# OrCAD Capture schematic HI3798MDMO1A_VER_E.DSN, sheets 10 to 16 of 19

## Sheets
10 SHEET08: size Custom
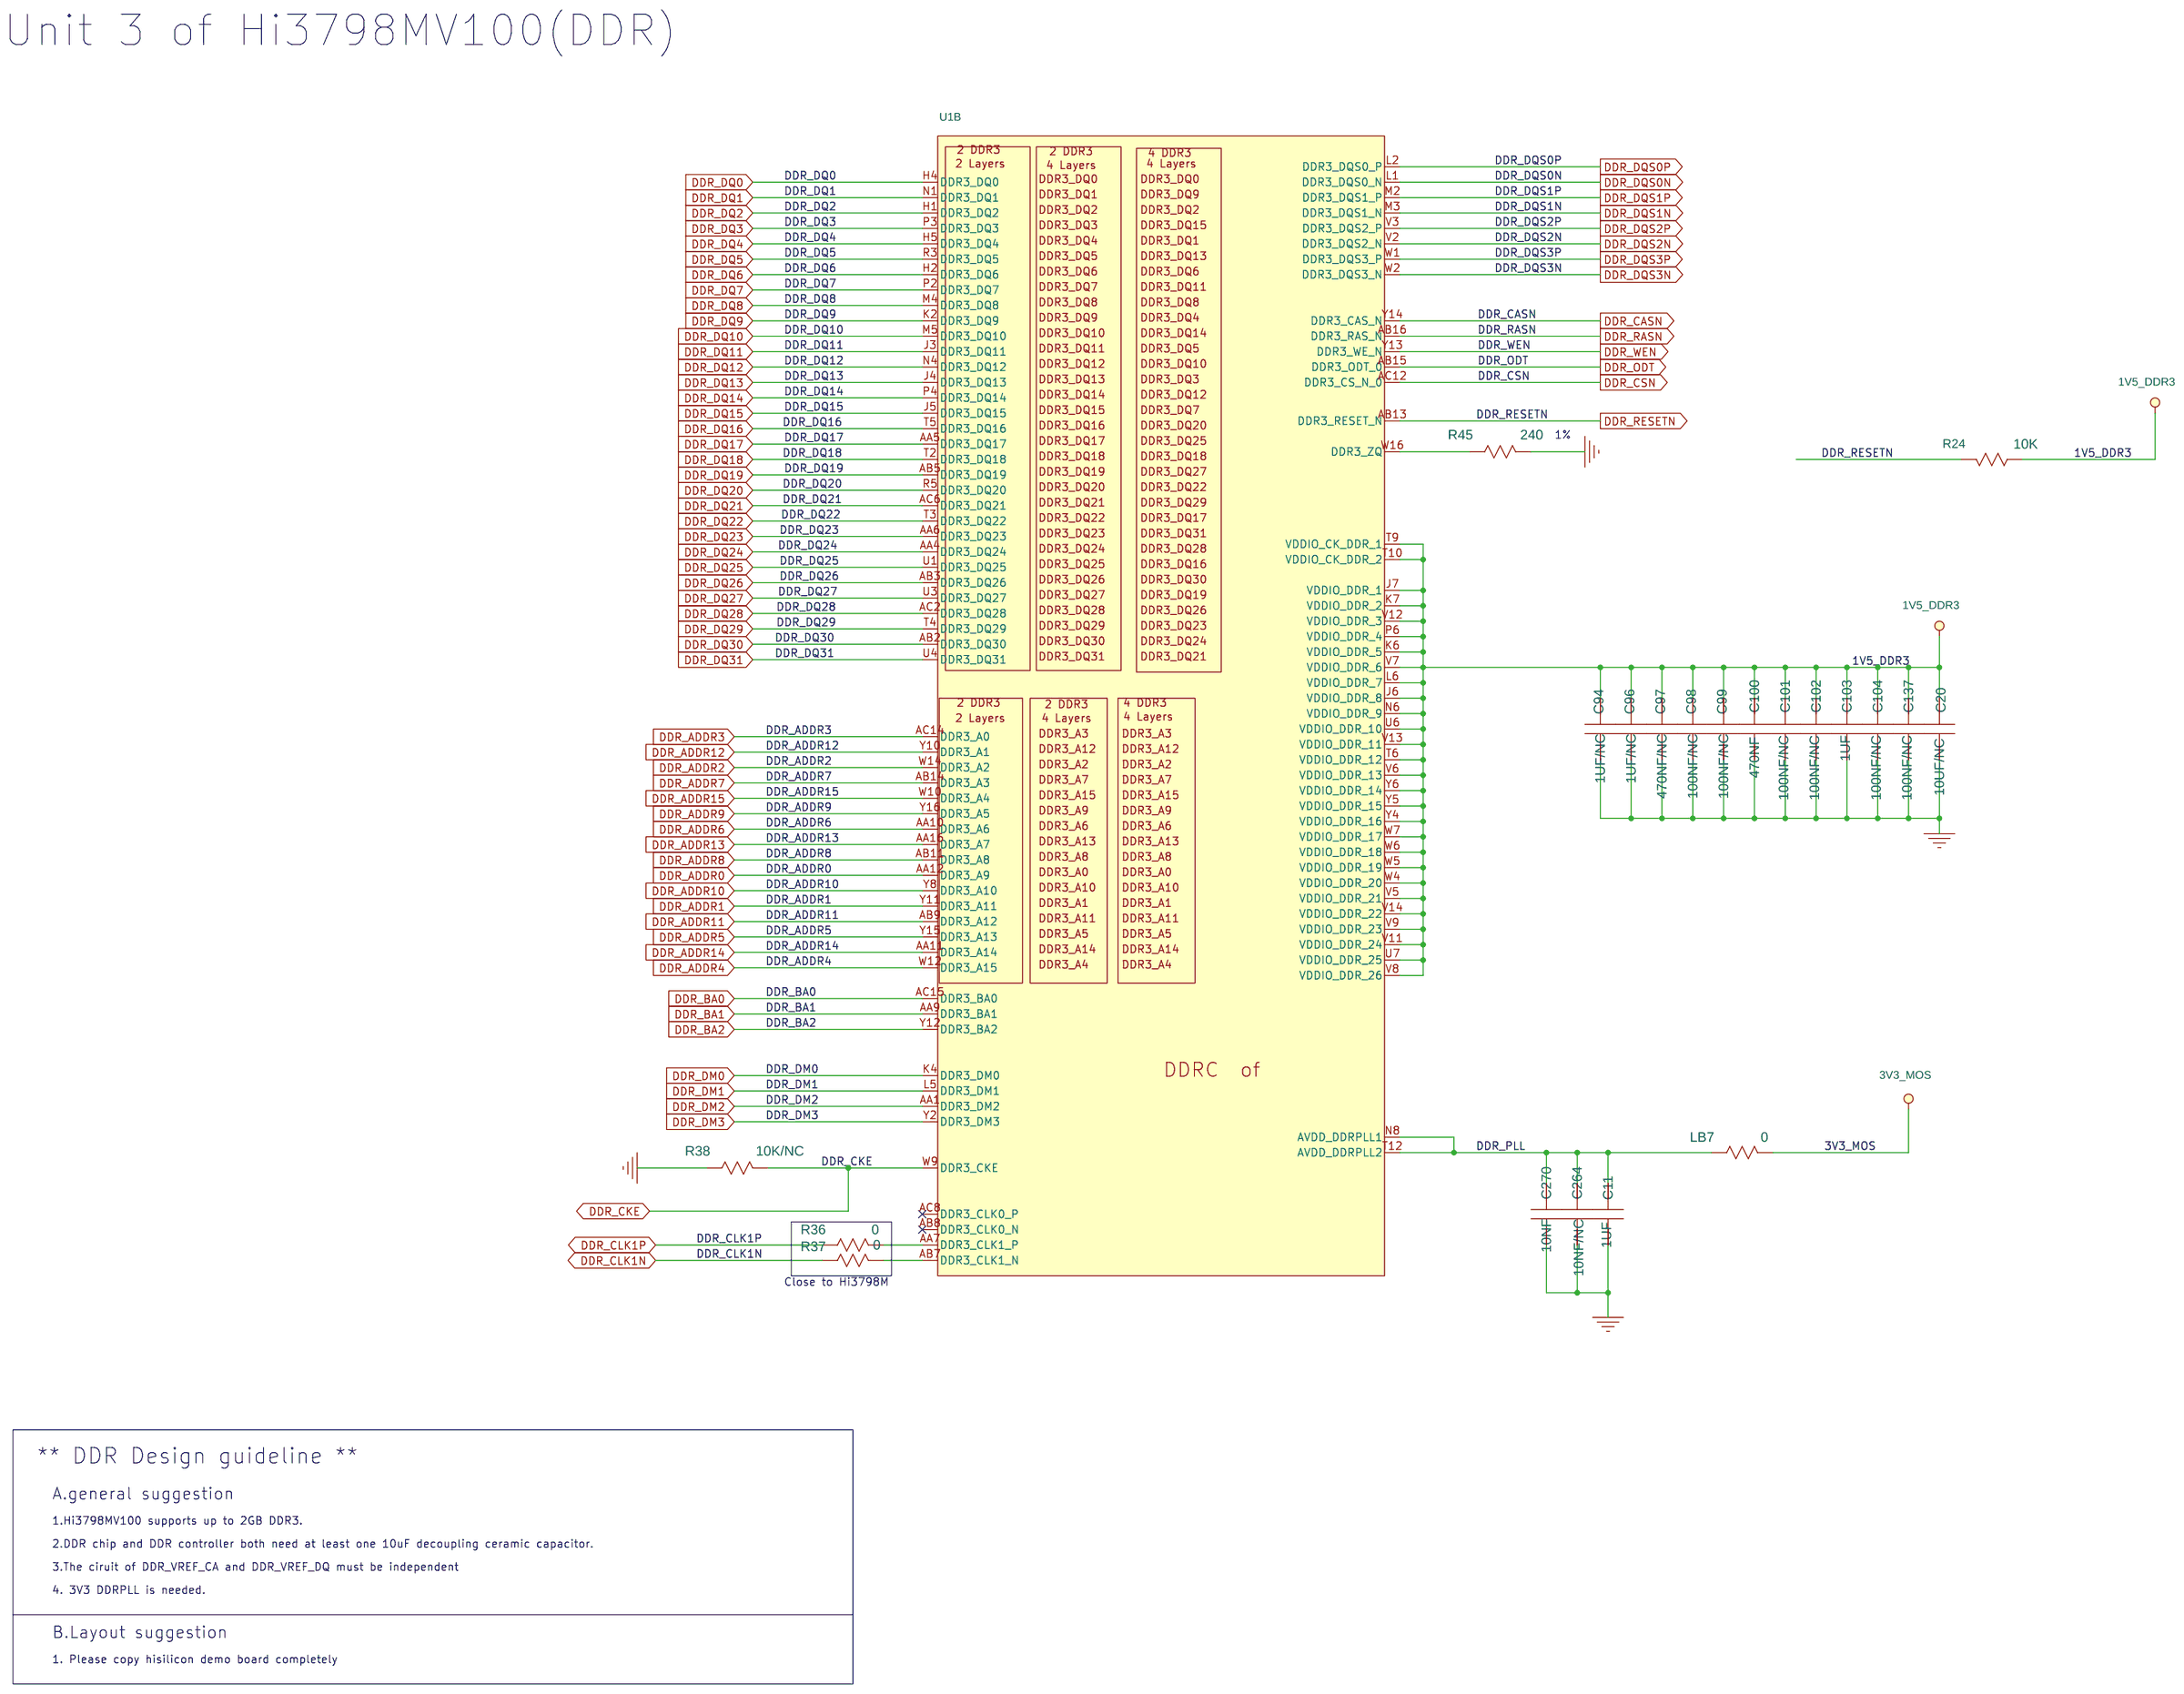
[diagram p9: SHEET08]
11 SHEET09: size Custom
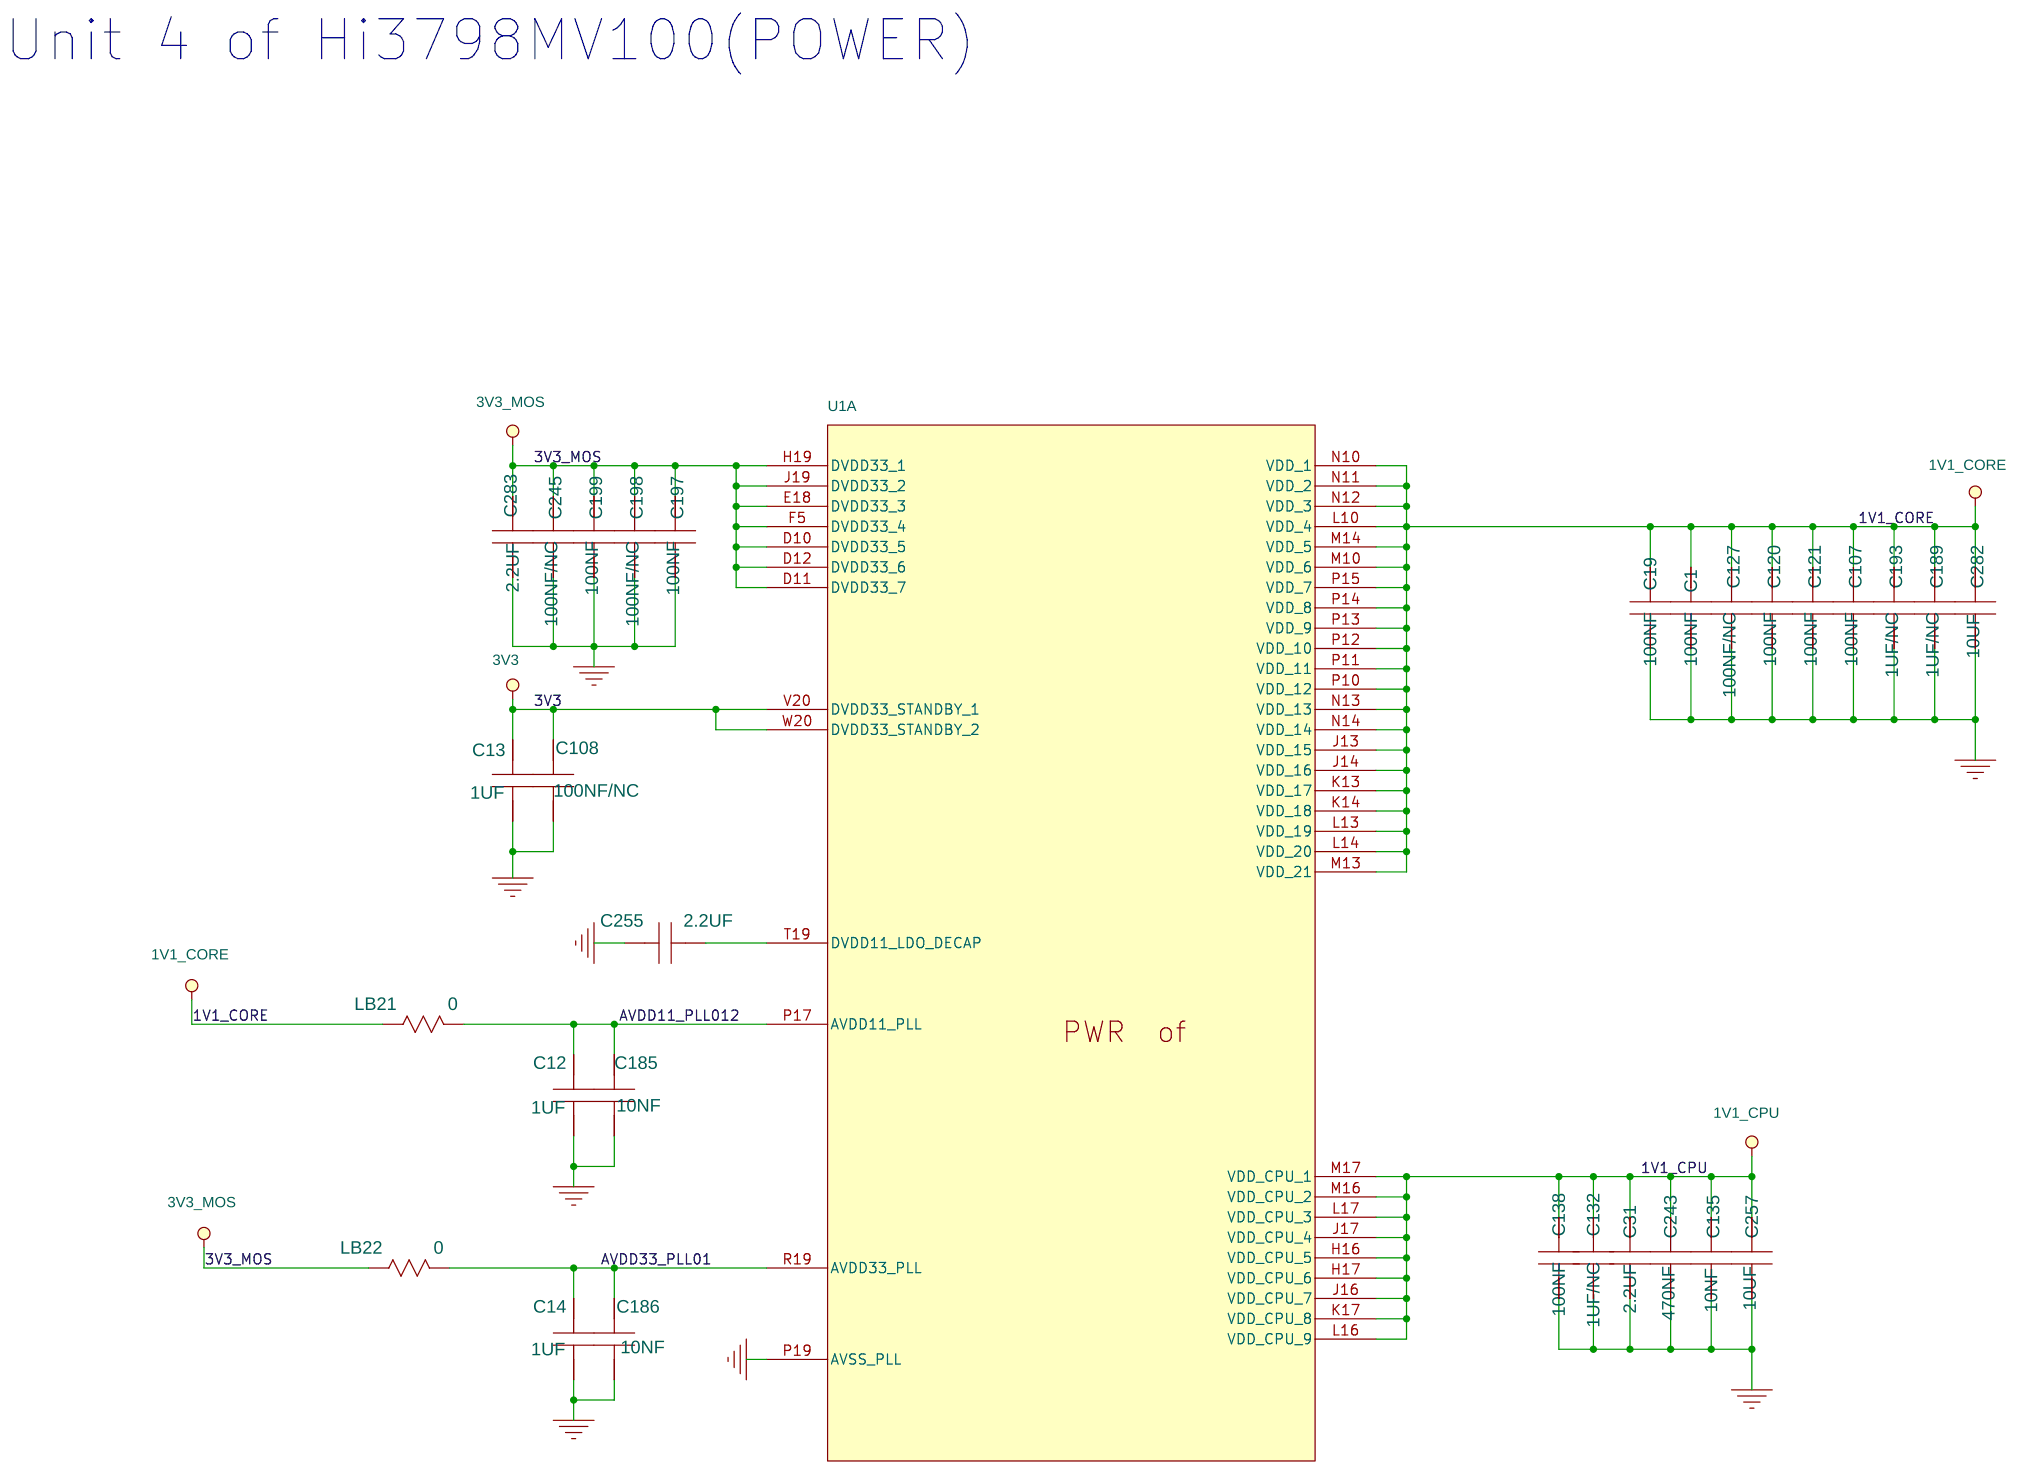
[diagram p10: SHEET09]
12 SHEET10: size Custom
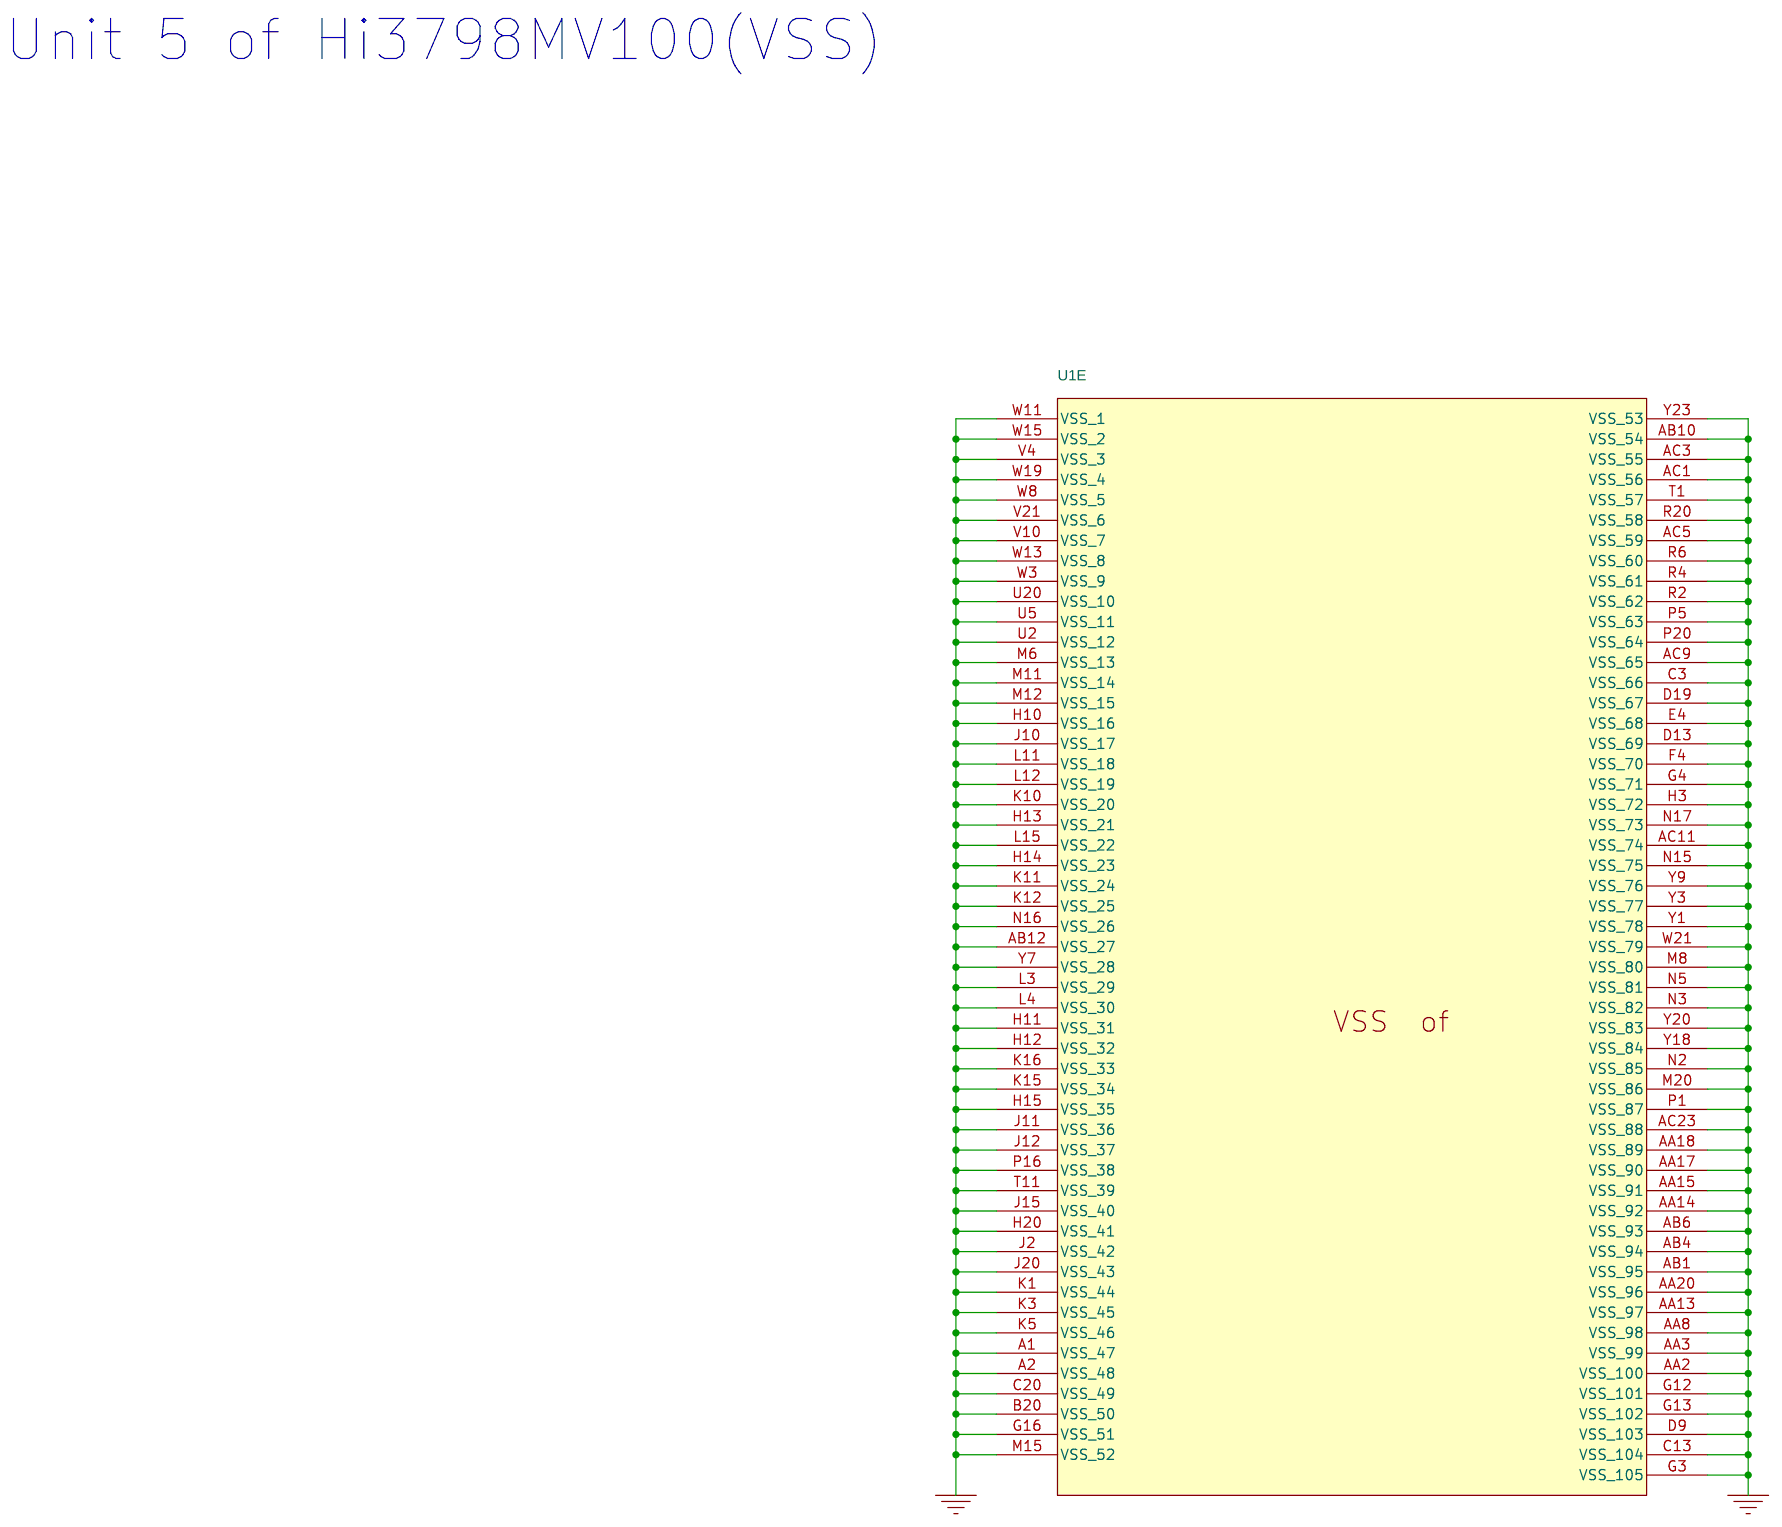
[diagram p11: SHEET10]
13 SHEET13: size Custom
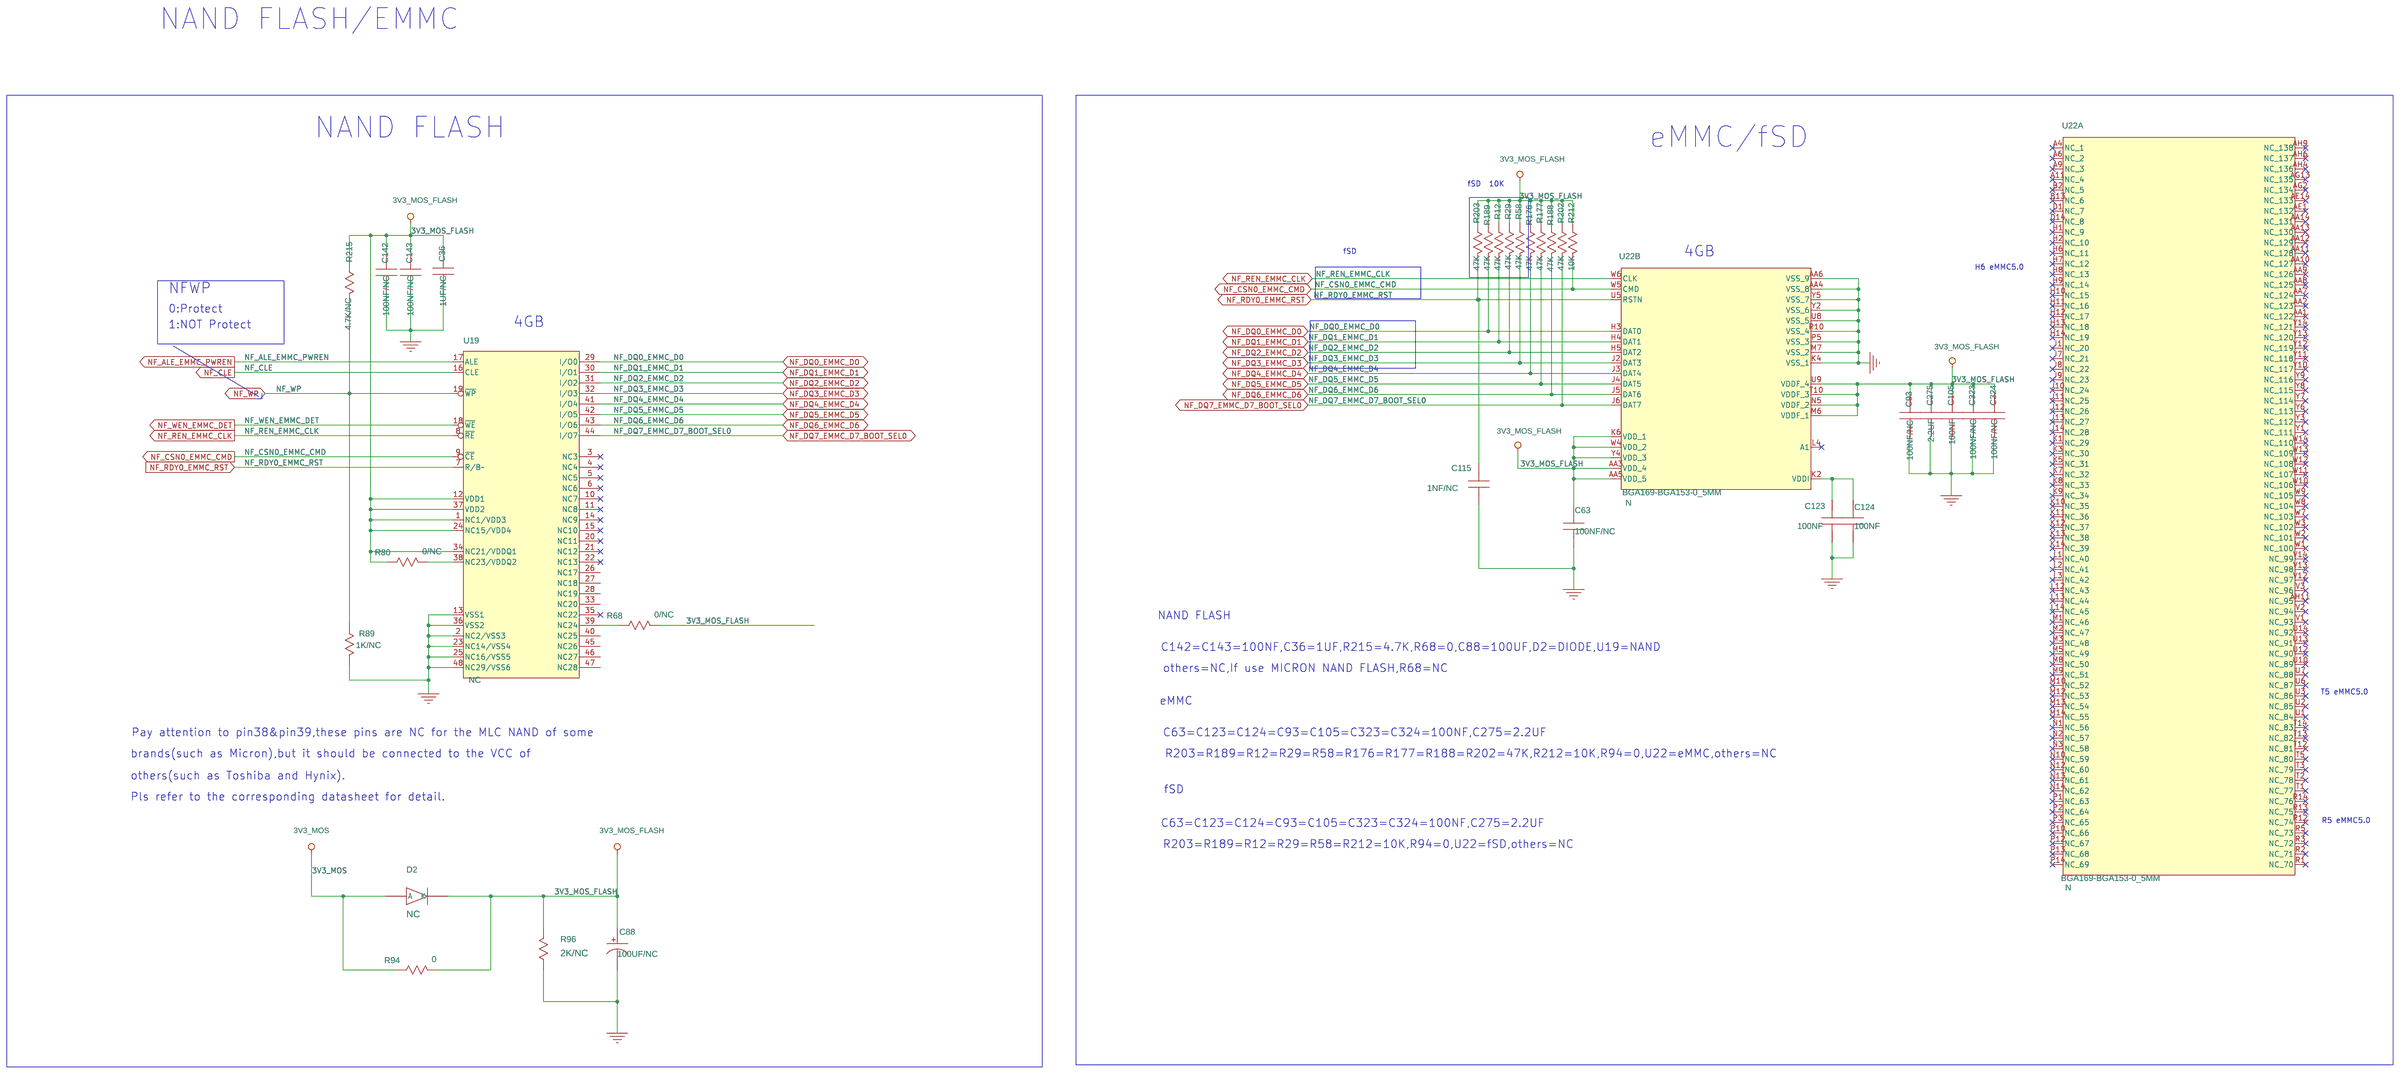
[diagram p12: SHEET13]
14 SHEET14: size Custom
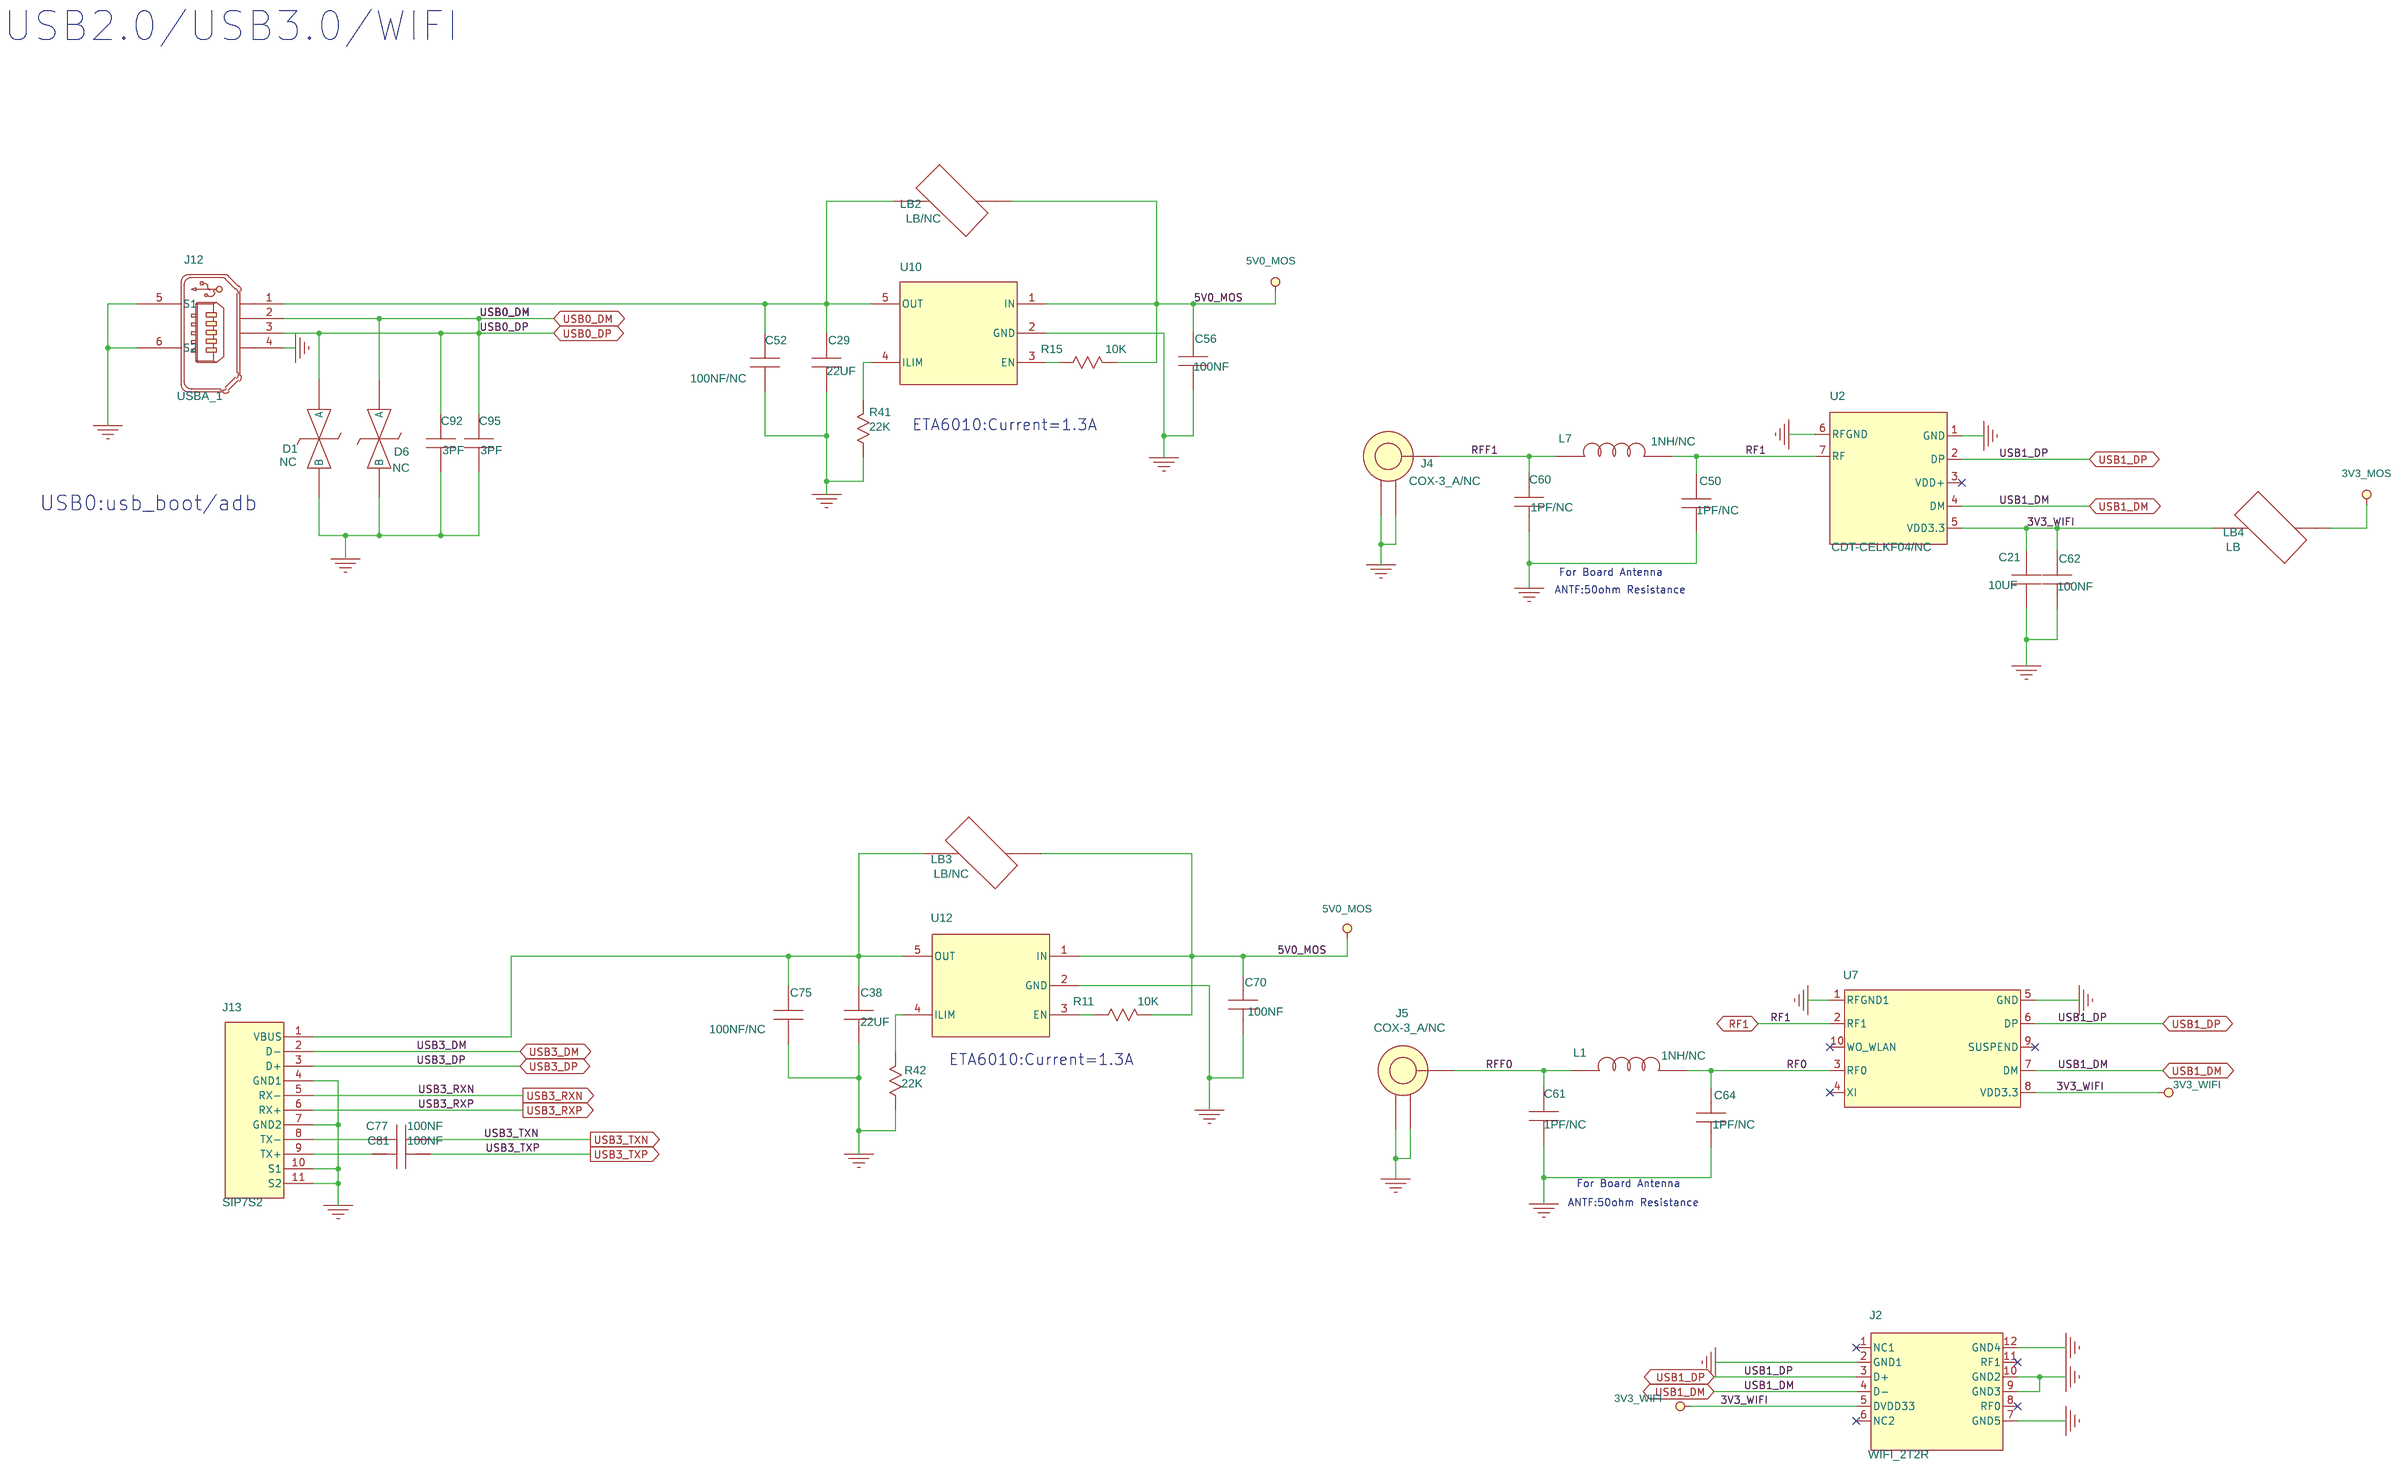
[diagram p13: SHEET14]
15 SHEET15: size Custom
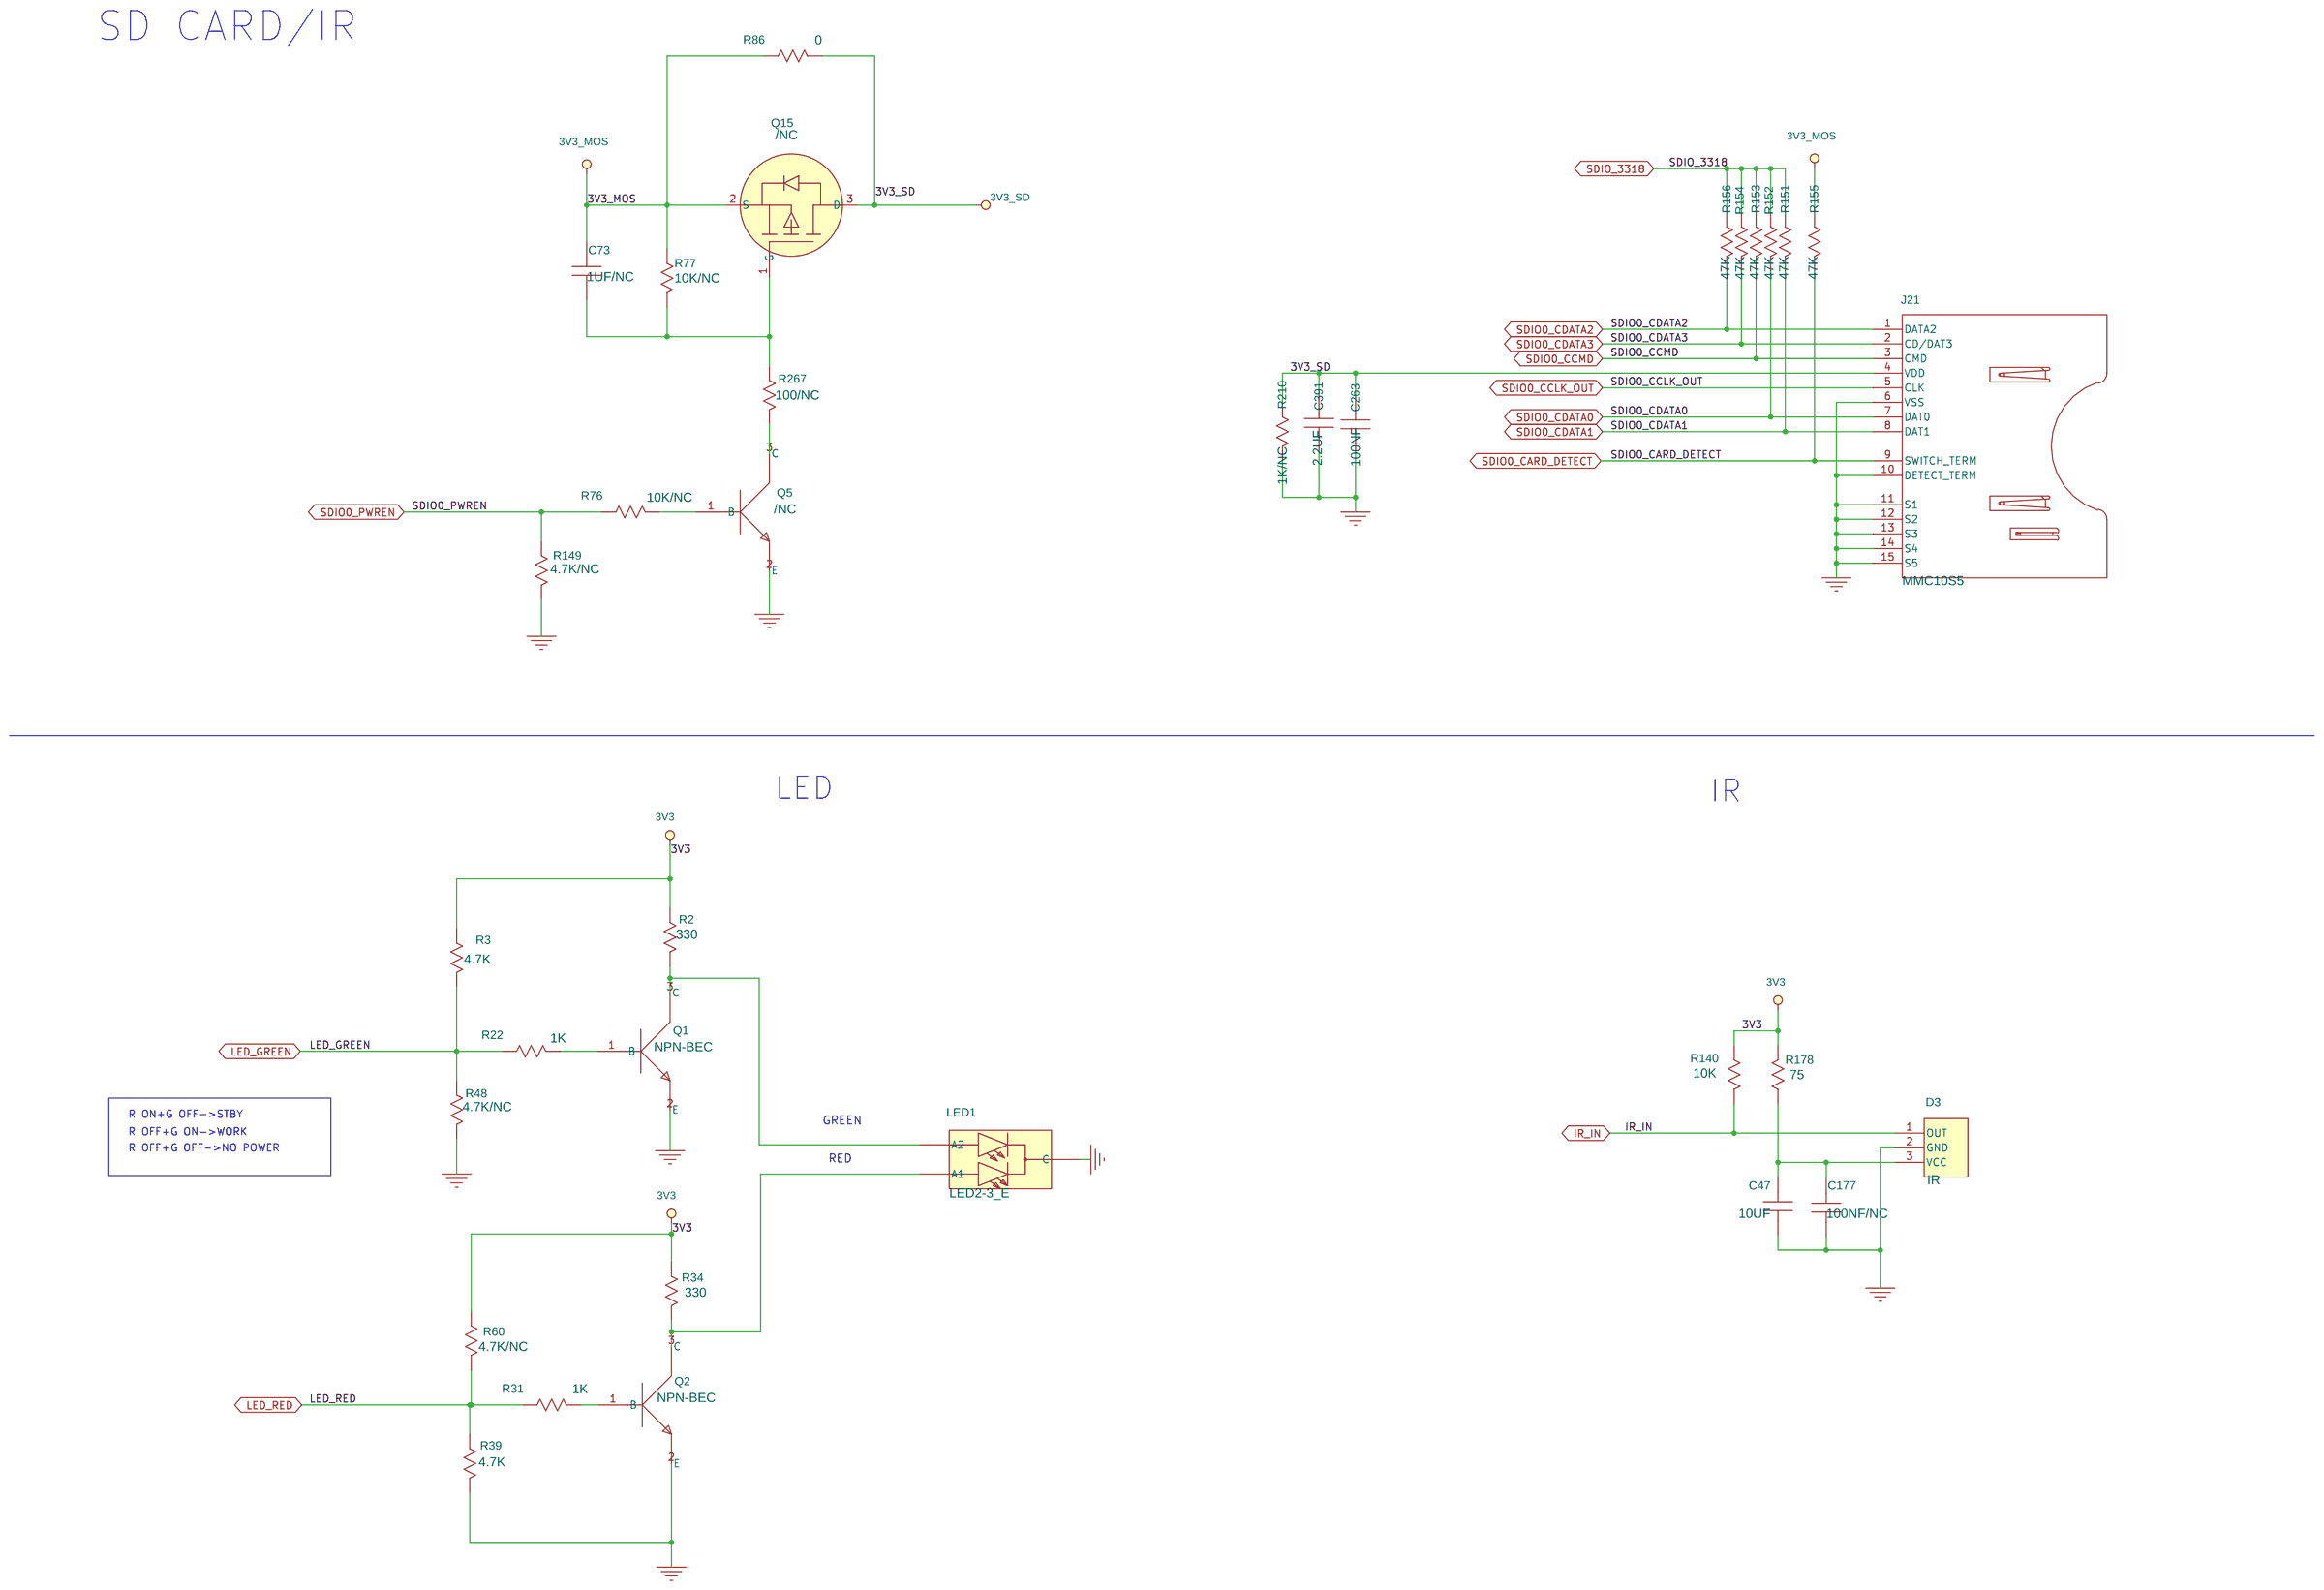
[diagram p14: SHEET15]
16 SHEET16: size Custom
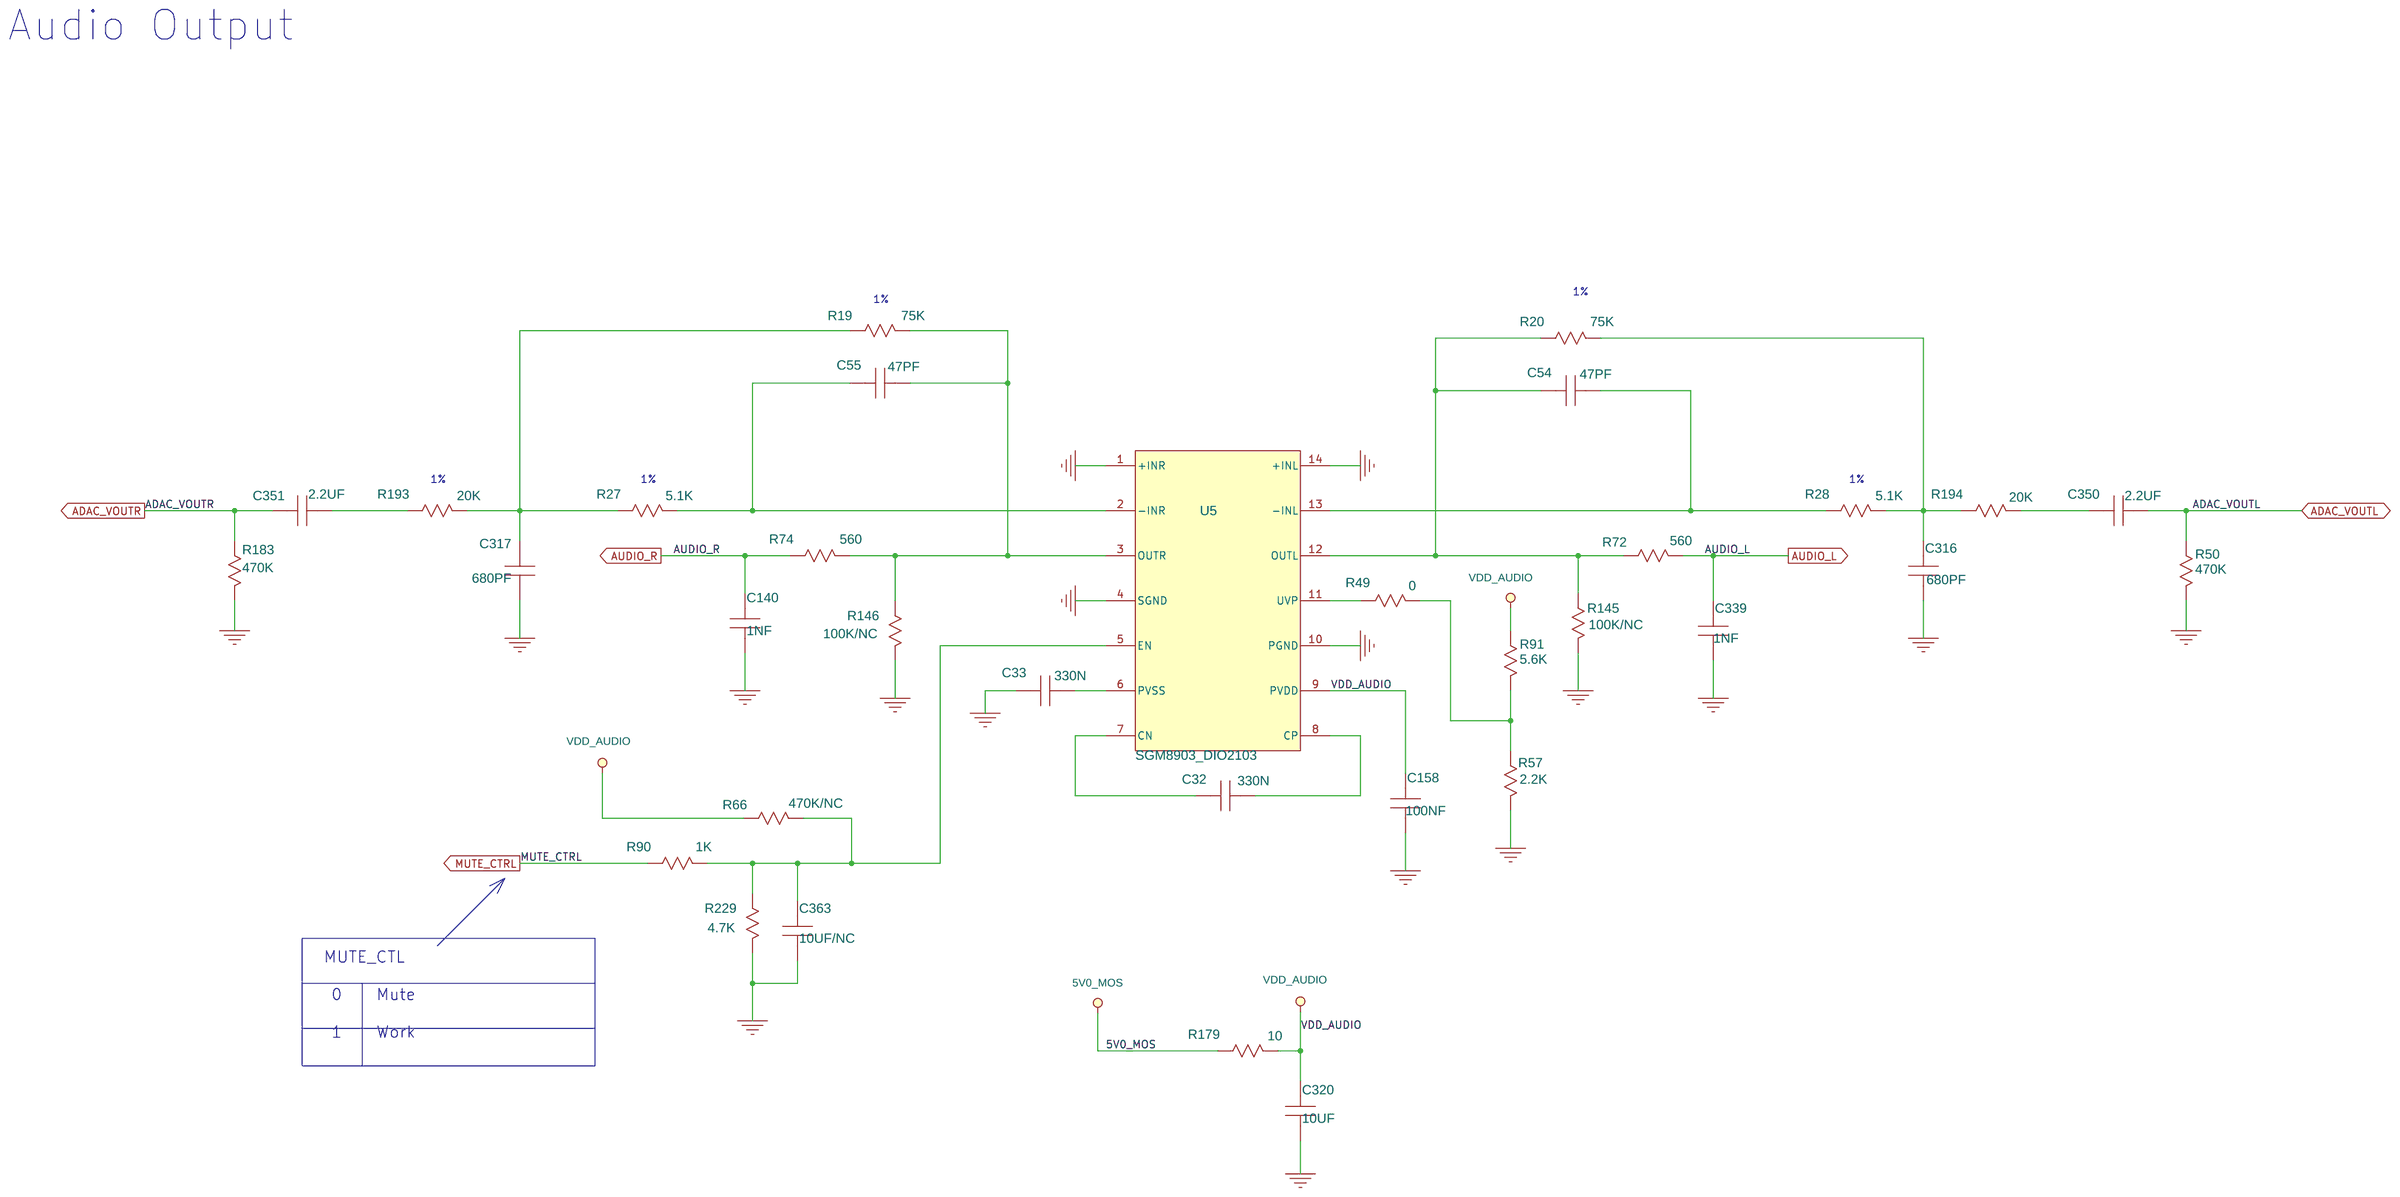
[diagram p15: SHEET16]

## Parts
sheet SHEET08
C11  1UF  [SC0603]
C20  10UF/NC  [SC0603]
C94  1UF/NC  [SC0402]
C96  1UF/NC  [SC0402]
C97  470NF/NC  [SC0402]
C98  100NF/NC  [SC0402]
C99  100NF/NC  [SC0402]
C100  470NF  [SC0402]
C101  100NF/NC  [SC0402]
C102  100NF/NC  [SC0402]
C103  1UF  [SC0402]
C104  100NF/NC  [SC0402]
C137  100NF/NC  [SC0402]
C264  10NF/NC  [SC0402]
C270  10NF  [SC0402]
LB7  0  [SL0603]
R24  10K  [SR0402]
R36  0  [SR0402]
R37  0  [SR0402]
R38  10K/NC  [SR0402]
R45  240  [SR0402]
sheet SHEET09
C1  100NF  [SC0402]
C12  1UF  [SC0402]
C13  1UF  [SC0603]
C14  1UF  [SC0402]
C19  100NF  [SC0402]
C31  2.2UF  [HSC0402]
C107  100NF  [SC0402]
C108  100NF/NC  [SC0402]
C120  100NF  [SC0402]
C121  100NF  [SC0402]
C127  100NF/NC  [SC0402]
C132  1UF/NC  [SC0402]
C135  10NF  [HSC0402]
C138  100NF  [SC0402]
C185  10NF  [SC0402]
C186  10NF  [SC0402]
C189  1UF/NC  [SC0402]
C193  1UF/NC  [SC0402]
C197  100NF  [SC0402]
C198  100NF/NC  [SC0402]
C199  100NF  [SC0402]
C243  470NF  [SC0402]
C245  100NF/NC  [SC0402]
C255  2.2UF  [HSC0402]
C257  10UF  [SC0603]
C282  10UF  [SC0603]
C283  2.2UF  [SC0603]
LB21  0  [SL0603]
LB22  0  [SL0603]
U1  S40V300_19X19  [TFBGA395-32-2323]  (sections A,B,C,D,E)
sheet SHEET13
C36  1UF/NC  [SC0603]
C63  100NF/NC  [SC0402]
C88  100UF/NC  [SAC6666]
C93  100NF/NC  [SC0402]
C105  100NF  [SC0402]
C115  1NF/NC  [SC0402]
C123  100NF  [SC0402]
C124  100NF  [SC0402]
C142  100NF/NC  [SC0402]
C143  100NF/NC  [SC0402]
C275  2.2UF  [SC0603]
C323  100NF/NC  [SC0402]
C324  100NF/NC  [SC0402]
D2  NC  [HSOD323A]
R12  47K  [SR0402]
R29  47K  [SR0402]
R58  47K  [SR0402]
R68  0/NC  [SR0402]
R80  0/NC  [SR0402]
R89  1K/NC  [SR0402]
R94  0  [SR1206]
R96  2K/NC  [SR0402]
R176  47K  [SR0402]
R177  47K  [SR0402]
R188  47K  [SR0402]
R189  47K  [SR0402]
R202  47K  [SR0402]
R203  47K  [SR0402]
R212  10K  [SR0402]
R215  4.7K/NC  [SR0402]
U19  NC  [SOP48-20-720B]
U22  N  [BGA169-BGA153-0_5MM]  (sections A,B)
sheet SHEET14
C21  10UF  [SC0603]
C29  22UF  [SC0805]
C38  22UF  [SC0805]
C50  1PF/NC  [SC0402]
C52  100NF/NC  [SC0603]
C56  100NF  [SC0603]
C60  1PF/NC  [SC0402]
C61  1PF/NC  [SC0402]
C62  100NF  [SC0603]
C64  1PF/NC  [SC0402]
C70  100NF  [SC0603]
C75  100NF/NC  [SC0603]
C77  100NF  [SC0402]
C81  100NF  [SC0402]
C92  3PF  [SC0402]
C95  3PF  [SC0402]
D1  NC  [SC0402]
D6  NC  [SC0402]
J2  WIFI_2T2R  [SIP12-2_0MM-1827]
J4  COX-3_A/NC  [HSCOX-AMC-TM-A]
J5  COX-3_A/NC  [HSCOX-AMC-TM-A]
J12  USBA_1  [USB4-1415]
J13  SIP7S2  [USB3_0_9P_DIP_MAINSUPER]
L1  1NH/NC  [SL0402]
L7  1NH/NC  [SL0402]
LB2  LB/NC  [SL0603]
LB3  LB/NC  [SL0603]
LB4  LB  [SL0805]
R11  10K  [SR0402]
R15  10K  [SR0402]
R41  22K  [SR0402]
R42  22K  [SR0402]
U2  CDT-CELKF04/NC  [CDTWIFI]
U7  NC  [CDTWIFI10]
U10  NC  [SOT23-5]
U12  NC  [SOT23-5]
sheet SHEET15
C47  10UF  [SC0603]
C73  1UF/NC  [SC0402]
C177  100NF/NC  [SC0402]
C263  100NF  [SC0603]
C391  2.2UF  [SC0603]
D3  IR  [SEN3-100C]
J21  MMC10S5  [MICRO_SD8-PUSH]
LED1  LED2-3_E  [LED3C-100C]
Q1  NPN-BEC  [SOT23]
Q2  NPN-BEC  [SOT23]
Q5  /NC  [SOT23]
Q15  /NC  [SOT23]
R2  330  [SR0402]
R3  4.7K  [SR0402]
R22  1K  [SR0402]
R31  1K  [SR0402]
R34  330  [SR0402]
R39  4.7K  [SR0402]
R48  4.7K/NC  [SR0402]
R60  4.7K/NC  [SR0402]
R76  10K/NC  [SR0603]
R77  10K/NC  [SR0603]
R86  0  [SR0603]
R140  10K  [SR0402]
R149  4.7K/NC  [SR0603]
R151  47K  [SR0402]
R152  47K  [SR0402]
R153  47K  [SR0402]
R154  47K  [SR0402]
R155  47K  [SR0402]
R156  47K  [SR0402]
R178  75  [SR0402]
R210  1K/NC  [SR0603]
R267  100/NC  [SR0603]
sheet SHEET16
C32  330N  [HSC0402]
C33  330N  [HSC0402]
C54  47PF  [SC0402]
C55  47PF  [SC0402]
C140  1NF  [SC0402]
C158  100NF  [SC0402]
C316  680PF  [SC0402]
C317  680PF  [SC0402]
C320  10UF  [SC0603]
C339  1NF  [SC0402]
C350  2.2UF  [SC0603]
C351  2.2UF  [SC0603]
C363  10UF/NC  [SC0603]
R19  75K  [SR0603]
R20  75K  [SR0603]
R27  5.1K  [SR0603]
R28  5.1K  [SR0603]
R49  0  [SR0402]
R50  470K  [SR0402]
R57  2.2K  [SR0402]
R66  470K/NC  [SR0402]
R72  560  [HSR0402]
R74  560  [HSR0402]
R90  1K  [SR0402]
R91  5.6K  [SR0402]
R145  100K/NC  [SR0402]
R146  100K/NC  [SR0402]
R179  10  [SR0603]
R183  470K  [SR0402]
R193  20K  [SR0402]
R194  20K  [SR0402]
R229  4.7K  [SR0402]
U5  SGM8903_DIO2103  [SGM8903]

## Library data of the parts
C11 C13 C36 = C: %182%%238%%182%%168%%185%%164%%215%%247%%181%%231%%209%%185%(V): 25; %195%%232%%202%%246%: SMD陶瓷电容-25V-1000NF-+/-10%-X7R-0603; %208%%161%%192%%224%%195%%251%%179%%198%: SMD陶瓷电容; CODE: 8070962; COMPONENT_HIGH_MAX: 0.9MM; DEVICE: CETMK107B7105KA_T
C20 = C: %182%%238%%182%%168%%185%%164%%215%%247%%181%%231%%209%%185%(V): 6.3; %195%%232%%202%%246%: SMD陶瓷电容-6.3V-10000NF-+/-10%-X7R-0805; %208%%161%%192%%224%%195%%251%%179%%198%: SMD陶瓷电容; CODE: 08070649; COMPONENT_HIGH_MAX: 0.9MM; DEVICE: C1608X5R0J106MT0A0E
C12 C14 C73 C94 C96 C103 C132 C189 C193 = C: %182%%238%%182%%168%%185%%164%%215%%247%%181%%231%%209%%185%(V): 10; %195%%232%%202%%246%: SMD陶瓷电容-10V-1000NF-+/-10%-X5R-0402-BT,TS16949; %208%%161%%192%%224%%195%%251%%179%%198%: SMD陶瓷电容; CODE: 8070612; COMPONENT_HIGH_MAX: 0.55MM; DEVICE: CV05X5R105K10AH
C97 C100 C243 = C: %182%%238%%182%%168%%185%%164%%215%%247%%181%%231%%209%%185%(V): 6.3; %195%%232%%202%%246%: SMD陶瓷电容-6.3V-470NF-+/-10%-X5R-0402; %208%%161%%192%%224%%195%%251%%179%%198%: SMD陶瓷电容; CODE: 8070625; COMPONENT_HIGH_MAX: 0.55MM; DEVICE: GRM155R60J474KE19D
C1 C19 C77 C81 C93 C98 C99 C101 C102 C104 C105 C107 C108 C115 C120 C121 C123 C124 C127 C137 C138 C197-C199 C245 C323 C324 = C: %182%%238%%182%%168%%185%%164%%215%%247%%181%%231%%209%%185%(V): 10; %195%%232%%202%%246%: SMD陶瓷电容-10V-100NF-+/-10%-X5R-0402; %208%%161%%192%%224%%195%%251%%179%%198%: SMD陶瓷电容; CODE: 8070561; COMPONENT_HIGH_MAX: 0.55MM; DEVICE: C0402C104K8PAC_7867
C135 C185 C186 C264 C270 = C: %182%%238%%182%%168%%185%%164%%215%%247%%181%%231%%209%%185%(V): 16; %195%%232%%202%%246%: SMD陶瓷电容-16V-10NF-+/-10%-X7R-0402-BT,TS16949; %208%%161%%192%%224%%195%%251%%179%%198%: SMD陶瓷电容; CODE: 8070449; COMPONENT_HIGH_MAX: 0.55MM; DEVICE: GRM155R71C103KA01D
LB7 LB21 LB22 = R: %182%%238%%182%%168%%185%%166%%194%%202%(W): 0.06; %195%%232%%202%%246%: 片式厚膜电阻器-0.0625W-0OHM-< 56MOHM-0402-1A-BT; %208%%161%%192%%224%%195%%251%%179%%198%: 片式厚膜电阻器; %215%%232%%214%%181%%212%%202%%208%%237%%198%%171%%178%%238%: < 50MOHM; CODE: 7090800; COMPONENT_HIGH_MAX: 0.4MM; DEVICE: RC0402JR_070R
R11 R15 R24 R212 = R: %182%%238%%182%%168%%185%%166%%194%%202%(W): 0.06; %195%%232%%202%%246%: 片式厚膜电阻器-0.0625W-10000OHM-+/-5%-0402-BT; %208%%161%%192%%224%%195%%251%%179%%198%: 片式厚膜电阻器; %215%%232%%214%%181%%212%%202%%208%%237%%198%%171%%178%%238%: +/-5%; CODE: 7090815; DEVICE: RC_02W103JT
R36 R37 R68 R80 = R: %182%%238%%182%%168%%185%%166%%194%%202%(W): 0.06; %195%%232%%202%%246%: 片式厚膜电阻器-0.0625W-0OHM-< 50MOHM-0402-1A-BT; %208%%161%%192%%224%%195%%251%%179%%198%: 片式厚膜电阻器; %215%%232%%214%%181%%212%%202%%208%%237%%198%%171%%178%%238%: < 50MOHM; CODE: 7090800; COMPONENT_HIGH_MAX: 0.4MM; DEVICE: RC0402JR_070R
R38 R140 = R: %182%%238%%182%%168%%185%%166%%194%%202%(W): 0.06; %195%%232%%202%%246%: 片式厚膜电阻器-0.0625W-10000OHM-+/-5%-0402-BT; %208%%161%%192%%224%%195%%251%%179%%198%: 片式厚膜电阻器; %215%%232%%214%%181%%212%%202%%208%%237%%198%%171%%178%%238%: +/-5%; CODE: 7090815; COMPONENT_HIGH_MAX: 0.4MM; DEVICE: RC_02W103JT
R45 = R: %182%%238%%182%%168%%185%%166%%194%%202%(W): 0.06; %195%%232%%202%%246%: 片式厚膜电阻器-0.0625W-240OHM-+/- 1%-0402-BT; %208%%161%%192%%224%%195%%251%%179%%198%: 片式厚膜电阻器; %215%%232%%214%%181%%212%%202%%208%%237%%198%%171%%178%%238%: +/- 1%; CODE: 7091782; COMPONENT_HIGH_MAX: 0.4MM; DEVICE: RC0402FR_07240RL
C31 C255 = C: %182%%238%%182%%168%%185%%164%%215%%247%%181%%231%%209%%185%(V): 6.3; %195%%232%%202%%246%: SMD陶瓷电容-6.3V-2200NF-+/-20%-X5R-0402-TS16949; %208%%161%%192%%224%%195%%251%%179%%198%: SMD陶瓷电容; CODE: 8070667; COMPONENT_HIGH_MAX: 0.6MM; DEVICE: GRM155R60J225ME15D
C21 C47 C257 C282 C320 C363 = C: %182%%238%%182%%168%%185%%164%%215%%247%%181%%231%%209%%185%(V): 6.3; %195%%232%%202%%246%: SMD陶瓷电容-6.3V-10000NF-+/-20%-X5R-0603-BT,TS16949; %208%%161%%192%%224%%195%%251%%179%%198%: SMD陶瓷电容; CODE: 8070649; COMPONENT_HIGH_MAX: 0.9MM; DEVICE: C1608X5R0J106MT0A0E
C283 = C: %182%%238%%182%%168%%185%%164%%215%%247%%181%%231%%209%%185%(V): 6.3; %195%%232%%202%%246%: SMD陶瓷电容-6.3V-2200NF-+/-10%-X5R-0603-BT; %208%%161%%192%%224%%195%%251%%179%%198%: SMD陶瓷电容; CODE: 8070563; COMPONENT_HIGH_MAX: 0.95MM; DEVICE: CM105X5R225K06AT
U1 = Hi3798MV100: DEVICE: HI3798MV100_A
C63 = C: %182%%238%%182%%168%%185%%164%%215%%247%%181%%231%%209%%185%(V): 50; %195%%232%%202%%246%: SMD陶瓷电容-50V-1NF-+/-10%-X7R-0402-BT; %208%%161%%192%%224%%195%%251%%179%%198%: SMD陶瓷电容; CODE: 8070531; COMPONENT_HIGH_MAX: 0.56MM; DEVICE: 04025C102KAT2A
C88 = CP: %182%%238%%182%%168%%185%%164%%215%%247%%181%%231%%209%%185%(V): 16; %195%%232%%202%%246%: 非固体SMD铝电容-16V-100UF-+/-20%-6.3*5.4MM-极性-105DEGC-1000H-片式,温度敏感器件-工艺耐温250DEGC,5S; %208%%161%%192%%224%%195%%251%%179%%198%: 非固体SMD铝电容; CODE: 8010269; COMPONENT_HIGH_MAX: 5.7MM; DEVICE: UWT1C101MCL1GB
C142 C143 C158 = C: %182%%238%%182%%168%%185%%164%%215%%247%%181%%231%%209%%185%(V): 16; %195%%232%%202%%246%: SMD陶瓷电容-16V-100NF-±10%-X7R-0402; %208%%161%%192%%224%%195%%251%%179%%198%: SMD陶瓷电容; CODE: 8070614; COMPONENT_HIGH_MAX: 0.6MM; DEVICE: RMEMK105BJ104KV_FR
C275 = C: %182%%238%%182%%168%%185%%164%%215%%247%%181%%231%%209%%185%(V): 6.3; %195%%232%%202%%246%: SMD陶瓷电容-6.3V-2200NF-+/-10%-X5R-0603; %208%%161%%192%%224%%195%%251%%179%%198%: SMD陶瓷电容; CODE: 8070563; COMPONENT_HIGH_MAX: 0.95MM; DEVICE: CM105X5R225K06AT
D2 = D_A: %195%%232%%202%%246%: 肖特基二极管-10V-3A-0.24V-SOD323-BT; %208%%161%%192%%224%%195%%251%%179%%198%: 肖特基二极管; CODE: 15010252; COMPONENT_HIGH_MAX: 1.1MM; DEVICE: BAT60BE6327
R12 R29 R49 R58 R151-R156 R176 R177 R188 R189 R202 R203 = R: %182%%238%%182%%168%%185%%166%%194%%202%(W): 0.06; %195%%232%%202%%246%: 片式厚膜电阻器-0.0625W-47000OHM-+/-5%-0402-ELOM; %208%%161%%192%%224%%195%%251%%179%%198%: 片式厚膜电阻器; %215%%232%%214%%181%%212%%202%%208%%237%%198%%171%%178%%238%: +/-5%; CODE: 7090819; DEVICE: RC0402JR_0747K
R89 R90 = R: %182%%238%%182%%168%%185%%166%%194%%202%(W): 0.06; %195%%232%%202%%246%: 片式厚膜电阻器-0.0625W-1000OHM-±5%-0402; %208%%161%%192%%224%%195%%251%%179%%198%: 片式厚膜电阻器; %215%%232%%214%%181%%212%%202%%208%%237%%198%%171%%178%%238%: ±5%; CODE: 7090809; COMPONENT_HIGH_MAX: 0.4MM; DEVICE: RC0402JR_071KL
R94 = R: %182%%238%%182%%168%%185%%166%%194%%202%(W): 0.06; %195%%232%%202%%246%: 片式厚膜电阻器-0.0625W-0OHM-< 50MOHM-0402-1A-BT; %208%%161%%192%%224%%195%%251%%179%%198%: 片式厚膜电阻器; %215%%232%%214%%181%%212%%202%%208%%237%%198%%171%%178%%238%: < 50MOHM; CODE: 07090002; COMPONENT_HIGH_MAX: 0.4MM; DEVICE: RC1206JR_070RL
R96 = R: %182%%238%%182%%168%%185%%166%%194%%202%(W): 0.06; %195%%232%%202%%246%: 片式厚膜电阻器-0.0625W-2000OHM-+/-1%-0402-BT; %208%%161%%192%%224%%195%%251%%179%%198%: 片式厚膜电阻器; %215%%232%%214%%181%%212%%202%%208%%237%%198%%171%%178%%238%: +/-1%; CODE: 7091354; COMPONENT_HIGH_MAX: 0.4MM; DEVICE: RC_02W2001FT
R215 = R: %182%%238%%182%%168%%185%%166%%194%%202%(W): 0.06; %195%%232%%202%%246%: 片式厚膜电阻器-0.0625W-4700OHM-+/-5%-0402; %208%%161%%192%%224%%195%%251%%179%%198%: 片式厚膜电阻器; %215%%232%%214%%181%%212%%202%%208%%237%%198%%171%%178%%238%: +/-5%; CODE: 7090793; COMPONENT_HIGH_MAX: 0.4MM; DEVICE: RK73B1ELTP472J
U19 = MLC_NAND_0: CODE: *
U22 = N_0: CaptureCellPackProp: NA
C29 C38 = C: %182%%238%%182%%168%%185%%164%%215%%247%%181%%231%%209%%185%(V): 6.3; %195%%232%%202%%246%: SMD陶瓷电容-6.3V-22000NF-+/-20%-X5R-0805-08070784编码拆分供华为技术使用; %208%%161%%192%%224%%195%%251%%179%%198%: SMD陶瓷电容; CODE: 8071114; COMPONENT_HIGH_MAX: 1.35MM; DEVICE: C2012X5R0J226MT000N
C50 C60 C61 C64 = C: %182%%238%%182%%168%%185%%164%%215%%247%%181%%231%%209%%185%(V): 50; %195%%232%%202%%246%: SMD陶瓷电容-50V-0.001NF-+/-0.1PF-NPO-0402-BT; %208%%161%%192%%224%%195%%251%%179%%198%: SMD陶瓷电容; CODE: 8070578; COMPONENT_HIGH_MAX: 0.55MM; DEVICE: GRM1555C1H1R0B
C52 C56 C62 C70 C75 C92 C95 C263 = C: %182%%238%%182%%168%%185%%164%%215%%247%%181%%231%%209%%185%(V): 50; %195%%232%%202%%246%: SMD陶瓷电容-50V-100NF-±10%-X7R-0603; %208%%161%%192%%224%%195%%251%%179%%198%: SMD陶瓷电容; CODE: 8070627; COMPONENT_HIGH_MAX: 0.9MM; DEVICE: C1608X7R1H104KT000N
D1 D6 = ULCE0505A015FR
J2 = WIFI_0
J4 J5 = COX-3_A: %195%%232%%202%%246%: 射频连接器-同轴连接器-50OHM-直式-MALE-SMT-终端专用-终端专用; %208%%161%%192%%224%%195%%251%%179%%198%: 射频连接器; CODE: 14240060; COMPONENT_HIGH_MAX: 1.45MM; DEVICE: 51_3612_50_H
J12 = USBA_1: CODE: 14080105
J13 = SIP7S2_0
L1 L7 = L: %195%%232%%202%%246%: 贴片电感器-0.001UH-5％-0.045OHM-1.36A-15DEGC-0402; %208%%161%%192%%224%%195%%251%%179%%198%: 贴片电感器; CODE: 10031232; COMPONENT_HIGH_MAX: 0.66MM; DEVICE: 0402CS_1N0XJLW
LB2 LB3 = LB_v2: %195%%232%%202%%246%: EMI磁珠-30OHM-0.05OHM-0.4A-0603-; %208%%161%%192%%224%%195%%251%%179%%198%: EMI磁珠; CODE: 10070003; COMPONENT_HIGH_MAX: 0.95MM; DEVICE: MGLB1608_030T_LF
LB4 = LB_v2: %195%%232%%202%%246%: EMI磁珠-+/-25%-220OHM-0.05OHM-2A-0805; %208%%161%%192%%224%%195%%251%%179%%198%: EMI磁珠; CODE: 10070012; COMPONENT_HIGH_MAX: 1.05MM; DEVICE: MGLB2012_220T_LF
R41 R42 = R: %182%%238%%182%%168%%185%%166%%194%%202%(W): 0.06; %195%%232%%202%%246%: 片式厚膜电阻器-0.0625W-22000OHM-+/-1%-0402; %208%%161%%192%%224%%195%%251%%179%%198%: 片式厚膜电阻器; %215%%232%%214%%181%%212%%202%%208%%237%%198%%171%%178%%238%: +/-1%; CODE: 7090798; COMPONENT_HIGH_MAX: 0.4MM; DEVICE: RK73H1ELTP2202F
U2 = CDT-CELKF04_0
U7 = CDT-CELKF10_0
U10 U12 = ETA6010: DEVICE: ETA6010_SGM2551A
C177 = C: %182%%238%%182%%168%%185%%164%%215%%247%%181%%231%%209%%185%(V): 16; %195%%232%%202%%246%: SMD陶瓷电容-16V-100NF-+/-10%-X7R-0402-BT; %208%%161%%192%%224%%195%%251%%179%%198%: SMD陶瓷电容; CODE: 8070614; COMPONENT_HIGH_MAX: 0.6MM; DEVICE: RMEMK105BJ104KV_FR
C350 C351 C391 = C: %182%%238%%182%%168%%185%%164%%215%%247%%181%%231%%209%%185%(V): 10; %195%%232%%202%%246%: SMD陶瓷电容-10V-2200NF-+/-10%-X5R-0603; %208%%161%%192%%224%%195%%251%%179%%198%: SMD陶瓷电容; CODE: 8070573; COMPONENT_HIGH_MAX: 0.9MM; DEVICE: GRM188R61A225KE34D
D3 = IRM-3638A_0: %195%%232%%202%%246%: 红外遥控接收头-5V-0.001A-0.015KM-38KHZ-940NM-7*8*3.75; %208%%161%%192%%224%%195%%251%%179%%198%: 红外遥控接收头; COMPONENT_HIGH_MAX: 6.95MM; DEVICE: TSOP4838
J21 = MMC10S5: %195%%232%%202%%246%: 板卡座类连接器-MICRO-SD卡座-8PIN-PUSH-PUSH-1.1MM-无锁扣-无-1MM-厚度1.45MM-终端专用; CODE: 14240249; COMPONENT_HIGH_MAX: 1.55MM; DEVICE: 5031820832
LED1 = LED2-3_E: %195%%232%%202%%246%: 发光二极管-0.25CD-红绿625NM/570NM-25MA-插装-共阴-终端专用-00500098; CODE: 15020190; COMPONENT_HIGH_MAX: 7.2MM; DEVICE: 209_3SYGSURC_S530_A3HW
Q1 Q2 Q5 = NPN-BEC: %195%%232%%202%%246%: 三极管-NPN-45V-100MA-225MW-200MV@100MA-SOT-23-180@2MA; %208%%161%%192%%224%%195%%251%%179%%198%: 三极管; CODE: 15050206; COMPONENT_HIGH_MAX: 1.26MM; DEVICE: BC847AE6327
Q15 = FETP-GSD: %195%%232%%202%%246%: MOSFET-P沟道--8V--3A-50MOHM--8V-SOT23; %208%%161%%192%%224%%195%%251%%179%%198%: MOSFET; CODE: 15060134; COMPONENT_HIGH_MAX: 1.11MM; DEVICE: IRLML6401TR
R2 R22 R31 R34 = R: %182%%238%%182%%168%%185%%166%%194%%202%(W): 0.06; %195%%232%%202%%246%: 片式厚膜电阻器-0.0625W-1000OHM-+/-5%-0402-BT; %208%%161%%192%%224%%195%%251%%179%%198%: 片式厚膜电阻器; %215%%232%%214%%181%%212%%202%%208%%237%%198%%171%%178%%238%: +/-5%; CODE: 7090809; COMPONENT_HIGH_MAX: 0.4MM; DEVICE: RC0402JR_071KL
R3 R39 R48 R60 R229 = R: %182%%238%%182%%168%%185%%166%%194%%202%(W): 0.06; %195%%232%%202%%246%: 片式厚膜电阻器-0.0625W-4700OHM-+/-5%-0402-BT; %208%%161%%192%%224%%195%%251%%179%%198%: 片式厚膜电阻器; %215%%232%%214%%181%%212%%202%%208%%237%%198%%171%%178%%238%: +/-5%; CODE: 7090793; COMPONENT_HIGH_MAX: 0.4MM; DEVICE: RK73B1ELTP472J
R76 R77 = R: %182%%238%%182%%168%%185%%166%%194%%202%(W): 0.1; %195%%232%%202%%246%: 片式厚膜电阻器-0.1W-10000OHM-+/-1%-0603; %208%%161%%192%%224%%195%%251%%179%%198%: 片式厚膜电阻器; %215%%232%%214%%181%%212%%202%%208%%237%%198%%171%%178%%238%: +/-1%; CODE: 7090889; COMPONENT_HIGH_MAX: 0.55MM; DEVICE: RC_03K1002FT
R86 = R: %182%%238%%182%%168%%185%%166%%194%%202%(W): 0.1; %195%%232%%202%%246%: 片式厚膜电阻器-0.1W-0OHM-<50MOHM-0603-1A-BT,TS16949; %208%%161%%192%%224%%195%%251%%179%%198%: 片式厚膜电阻器; %215%%232%%214%%181%%212%%202%%208%%237%%198%%171%%178%%238%: <50MOHM; CODE: 7090522; COMPONENT_HIGH_MAX: 0.55MM; DEVICE: RC0603JR_070RL
R149 = R: %182%%238%%182%%168%%185%%166%%194%%202%(W): 0.1; %195%%232%%202%%246%: 片式厚膜电阻器-0.1W-4700OHM-+/-5%-0603-抗硫化; %208%%161%%192%%224%%195%%251%%179%%198%: 片式厚膜电阻器; %215%%232%%214%%181%%212%%202%%208%%237%%198%%171%%178%%238%: +/-5%; CODE: 7090246; DEVICE: RC0603JR_074K7
R178 = R: %182%%238%%182%%168%%185%%166%%194%%202%(W): 0.06; %195%%232%%202%%246%: 片式厚膜电阻器-0.0625W-75OHM-+/-1%-0402; %208%%161%%192%%224%%195%%251%%179%%198%: 片式厚膜电阻器; %215%%232%%214%%181%%212%%202%%208%%237%%198%%171%%178%%238%: +/-1%; CODE: 7091321; COMPONENT_HIGH_MAX: 0.4MM; DEVICE: RC_02W750FT
R210 = R: %182%%238%%182%%168%%185%%166%%194%%202%(W): 0.1; %195%%232%%202%%246%: 片式厚膜电阻器-0.1W-1000OHM-+/-5%-0603; %208%%161%%192%%224%%195%%251%%179%%198%: 片式厚膜电阻器; %215%%232%%214%%181%%212%%202%%208%%237%%198%%171%%178%%238%: +/-5%; CODE: 7090277; COMPONENT_HIGH_MAX: 0.55MM; DEVICE: RC0603JR_071K
R267 = R: %182%%238%%182%%168%%185%%166%%194%%202%(W): 0.06; %195%%232%%202%%246%: 片式厚膜电阻器-0.1W-100OHM-±5%-0603; %208%%161%%192%%224%%195%%251%%179%%198%: 片式厚膜电阻器; %215%%232%%214%%181%%212%%202%%208%%237%%198%%171%%178%%238%: ±5%; CODE: 7090269; COMPONENT_HIGH_MAX: 0.55MM; DEVICE: RC0603JR_07100RL
C32 C33 = C: %195%%232%%202%%246%: SMD陶瓷电容-6.3V-330NF-+/-10%-X5R-0402-终端专用; %208%%161%%192%%224%%195%%251%%179%%198%: SMD陶瓷电容; CODE: 8070953; COMPONENT_HIGH_MAX: 0.55MM; DEVICE: C1005X5R0J334K
C54 C55 = C: %182%%238%%182%%168%%185%%164%%215%%247%%181%%231%%209%%185%(V): 50; %195%%232%%202%%246%: SMD陶瓷电容-50V-0.047NF-+/-5%-NP0-0402; %208%%161%%192%%224%%195%%251%%179%%198%: SMD陶瓷电容; CODE: 8070549; COMPONENT_HIGH_MAX: 0.55MM; DEVICE: C0402C470J5GAC_7867
C140 C339 = C: %182%%238%%182%%168%%185%%164%%215%%247%%181%%231%%209%%185%(V): 50; %195%%232%%202%%246%: SMD陶瓷电容-50V-1NF-+/-10%-X7R-0402-BT; %208%%161%%192%%224%%195%%251%%179%%198%: SMD陶瓷电容; CODE: 8070531; COMPONENT_HIGH_MAX: 0.55MM; DEVICE: 04025C102KAT2A
C316 C317 = C: %182%%238%%182%%168%%185%%164%%215%%247%%181%%231%%209%%185%(V): 50; %195%%232%%202%%246%: SMD陶瓷电容-50V-0.68NF-+/-5%-NP0-0402-供电专用-供电专用; %208%%161%%192%%224%%195%%251%%179%%198%: SMD陶瓷电容; CODE: 8070853; COMPONENT_HIGH_MAX: 0.55MM; DEVICE: C0402C681J5GAC7867
R19 R20 = R: %182%%238%%182%%168%%185%%166%%194%%202%(W): 0.1; %195%%232%%202%%246%: 片式厚膜电阻器-0.1W-75000OHM-+/-1% -0603; %208%%161%%192%%224%%195%%251%%179%%198%: 片式厚膜电阻器; %215%%232%%214%%181%%212%%202%%208%%237%%198%%171%%178%%238%: +/-1%; CODE: 7091238; COMPONENT_HIGH_MAX: 0.55MM; DEVICE: RK73H1JTTD7502F
R27 R28 = R: %182%%238%%182%%168%%185%%166%%194%%202%(W): 0.1; %195%%232%%202%%246%: 片式厚膜电阻器-0.1W-5100OHM-+/-1%-0603; %208%%161%%192%%224%%195%%251%%179%%198%: 片式厚膜电阻器; %215%%232%%214%%181%%212%%202%%208%%237%%198%%171%%178%%238%: +/-1%; CODE: 7091295; COMPONENT_HIGH_MAX: 0.55MM; DEVICE: RC0603FR_075K1L
R50 R183 = R: %182%%238%%182%%168%%185%%166%%194%%202%(W): 0.06; %195%%232%%202%%246%: 片式厚膜电阻器-0.0625W-470000OHM-±1%-0402; %208%%161%%192%%224%%195%%251%%179%%198%: 片式厚膜电阻器; %215%%232%%214%%181%%212%%202%%208%%237%%198%%171%%178%%238%: ±1%; CODE: 7090855; COMPONENT_HIGH_MAX: 0.4MM; DEVICE: RK73H1ETTP4703F
R57 = R: %182%%238%%182%%168%%185%%166%%194%%202%(W): 0.06; %195%%232%%202%%246%: 片式厚膜电阻器-0.0625W-2200OHM-+/-1%-0402--供电专用-07090810-供电专用; %208%%161%%192%%224%%195%%251%%179%%198%: 片式厚膜电阻器; %215%%232%%214%%181%%212%%202%%208%%237%%198%%171%%178%%238%: +/-1%; CODE: 7091537; COMPONENT_HIGH_MAX: 0.4MM; DEVICE: RC0402FR_072K2L2
R66 = R: %182%%238%%182%%168%%185%%166%%194%%202%(W): 0.06; %195%%232%%202%%246%: 片式厚膜电阻器-0.0625W-470000OHM-+/-1%-0402; %208%%161%%192%%224%%195%%251%%179%%198%: 片式厚膜电阻器; %215%%232%%214%%181%%212%%202%%208%%237%%198%%171%%178%%238%: +/-1%; CODE: 7090855; COMPONENT_HIGH_MAX: 0.4MM; DEVICE: RK73H1ETTP4703F
R72 R74 = R: %195%%232%%202%%246%: 片式厚膜电阻器-0.0625W-560OHM-+/-5%-0402-终端专用-终端专用; %208%%161%%192%%224%%195%%251%%179%%198%: 片式厚膜电阻器; CODE: 7091285; COMPONENT_HIGH_MAX: 0.4MM; DEVICE: RC0402JR_07560RL
R91 = R: %182%%238%%182%%168%%185%%166%%194%%202%(W): 0.06; %195%%232%%202%%246%: 片式厚膜电阻器-0.0625W-5600OHM-+/-1%-0402-BT; %208%%161%%192%%224%%195%%251%%179%%198%: 片式厚膜电阻器; %215%%232%%214%%181%%212%%202%%208%%237%%198%%171%%178%%238%: +/-1%; CODE: 7091275; COMPONENT_HIGH_MAX: 0.4MM; DEVICE: RK73H1ETTP5601F
R145 R146 = R: %182%%238%%182%%168%%185%%166%%194%%202%(W): 0.06; %195%%232%%202%%246%: 片式厚膜电阻器-0.0625W-100000OHM-+/-5%-0402-BT; %208%%161%%192%%224%%195%%251%%179%%198%: 片式厚膜电阻器; %215%%232%%214%%181%%212%%202%%208%%237%%198%%171%%178%%238%: +/-5%; CODE: 7090831; COMPONENT_HIGH_MAX: 0.4MM; DEVICE: RK73B1ELTP104J
R179 = R: %182%%238%%182%%168%%185%%166%%194%%202%(W): 0.1; %195%%232%%202%%246%: 片式厚膜电阻器-0.1W-10OHM-+/-5%-0603-TS16949; %208%%161%%192%%224%%195%%251%%179%%198%: 片式厚膜电阻器; %215%%232%%214%%181%%212%%202%%208%%237%%198%%171%%178%%238%: +/-5%; CODE: 7090264; COMPONENT_HIGH_MAX: 0.55MM; DEVICE: RC0603JR_0710R
R193 R194 = R: %182%%238%%182%%168%%185%%166%%194%%202%(W): 0.06; %195%%232%%202%%246%: 片式厚膜电阻器-0.0625W-20000OHM-+/-1%-0402-TS16949; %208%%161%%192%%224%%195%%251%%179%%198%: 片式厚膜电阻器; %215%%232%%214%%181%%212%%202%%208%%237%%198%%171%%178%%238%: +/-1%; CODE: 7091374; COMPONENT_HIGH_MAX: 0.4MM; DEVICE: RC_02W2002FT
U5 = SGM8903

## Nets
1V1_CORE: C1.1(A) C19.1(A) C107.1(A) C120.1(A) C121.1(A) C127.1(A) C189.1(A) C193.1(A) C282.1(A) LB21.1(A) U1.J13(VDD_15) U1.J14(VDD_16) U1.K13(VDD_17) U1.K14(VDD_18) U1.L10(VDD_4) U1.L13(VDD_19) U1.L14(VDD_20) U1.M10(VDD_6) U1.M13(VDD_21) U1.M14(VDD_5) U1.N10(VDD_1) U1.N11(VDD_2) U1.N12(VDD_3) U1.N13(VDD_13) U1.N14(VDD_14) U1.P10(VDD_12) U1.P11(VDD_11) U1.P12(VDD_10) U1.P13(VDD_9) U1.P14(VDD_8) U1.P15(VDD_7) ; also on sheet 6 8 9
1V1_CPU: C31.1(A) C132.1(A) C135.1(A) C138.1(A) C243.1(A) C257.1(A) U1.H16(VDD_CPU_5) U1.H17(VDD_CPU_6) U1.J16(VDD_CPU_7) U1.J17(VDD_CPU_4) U1.K17(VDD_CPU_8) U1.L16(VDD_CPU_9) U1.L17(VDD_CPU_3) U1.M16(VDD_CPU_2) U1.M17(VDD_CPU_1) ; also on sheet 6
1V5_DDR3: C20.1(A) C94.1(A) C96.1(A) C97.1(A) C98.1(A) C99.1(A) C100.1(A) C101.1(A) C102.1(A) C103.1(A) C104.1(A) C137.1(A) R24.2(B) U1.J6(VDDIO_DDR_8) U1.J7(VDDIO_DDR_1) U1.K6(VDDIO_DDR_5) U1.K7(VDDIO_DDR_2) U1.L6(VDDIO_DDR_7) U1.N6(VDDIO_DDR_9) U1.P6(VDDIO_DDR_4) U1.T6(VDDIO_DDR_12) U1.T9(VDDIO_CK_DDR_1) U1.T10(VDDIO_CK_DDR_2) U1.U6(VDDIO_DDR_10) U1.U7(VDDIO_DDR_25) U1.V5(VDDIO_DDR_21) U1.V6(VDDIO_DDR_13) U1.V7(VDDIO_DDR_6) U1.V8(VDDIO_DDR_26) U1.V9(VDDIO_DDR_23) U1.V11(VDDIO_DDR_24) U1.V12(VDDIO_DDR_3) U1.V13(VDDIO_DDR_11) U1.V14(VDDIO_DDR_22) U1.W4(VDDIO_DDR_20) U1.W5(VDDIO_DDR_19) U1.W6(VDDIO_DDR_18) U1.W7(VDDIO_DDR_17) U1.Y4(VDDIO_DDR_16) U1.Y5(VDDIO_DDR_15) U1.Y6(VDDIO_DDR_14) ; also on sheet 1 2 6
3V3: C13.1(A) C108.1(A) R2.1(A) R3.1(A) R34.1(A) R60.1(A) R140.2(B) R178.2(B) U1.V20(DVDD33_STANDBY_1) U1.W20(DVDD33_STANDBY_2) ; also on sheet 6 7 8 17
3V3_MOS: C73.1(A) C197.1(A) C198.1(A) C199.1(A) C245.1(A) C283.1(A) D2.2(A) LB4.2 LB7.2(B) LB22.1(A) Q15.2(S) R77.1(A) R86.1(A) R94.1(A) R155.1(A) U1.D10(DVDD33_5) U1.D11(DVDD33_7) U1.D12(DVDD33_6) U1.E18(DVDD33_3) U1.F5(DVDD33_4) U1.H19(DVDD33_1) U1.J19(DVDD33_2) ; also on sheet 7 8 9 17 18 19
3V3_MOS_FLASH: C36.1(A) C63.1(A) C88.1 C93.1(A) C105.1(A) C142.1(A) C143.1(A) C275.1(A) C323.1(A) C324.1(A) D2.1(K) R12.1(A) R29.1(A) R58.1(A) R68.2(B) R80.1(A) R94.2(B) R96.2(B) R176.1(A) R177.1(A) R188.1(A) R189.1(A) R202.1(A) R203.1(A) R212.1(A) R215.1(A) U19.1(NC1/VDD3) U19.12(VDD1) U19.24(NC15/VDD4) U19.34(NC21/VDDQ1) U19.37(VDD2) U22.AA3(VDD_4) U22.AA5(VDD_5) U22.K6(VDD_1) U22.M6(VDDF_1) U22.N5(VDDF_2) U22.T10(VDDF_3) U22.U9(VDDF_4) U22.W4(VDD_2) U22.Y4(VDD_3)
3V3_SD: C263.1(A) C391.1(A) J21.4(VDD) Q15.3(D) R86.2(B) R210.1(A)
3V3_WIFI: C21.1(A) C62.1(A) J2.5(DVDD33) LB4.1 U2.5(VDD3.3) U7.8(VDD3.3)
5V0_MOS: C56.1(A) C70.1(A) LB2.2 LB3.2 R11.2(B) R15.2(B) R179.1(A) U10.1(IN) U12.1(IN) ; also on sheet 7 19
AVDD11_PLL012: C12.1(A) C185.1(A) LB21.2(B) U1.P17(AVDD11_PLL)
AVDD33_PLL01: C14.1(A) C186.1(A) LB22.2(B) U1.R19(AVDD33_PLL)
GND: C1.2(B) C11.2(B) C12.2(B) C13.2(B) C14.2(B) C19.2(B) C20.2(B) C21.2(B) C29.2(B) C31.2(B) C33.1(A) C36.2(B) C38.2(B) C47.2(B) C50.2(B) C52.2(B) C56.2(B) C60.2(B) C61.2(B) C62.2(B) C63.2(B) C64.2(B) C70.2(B) C75.2(B) C88.2 C92.2(B) C93.2(B) C94.2(B) C95.2(B) C96.2(B) C97.2(B) C98.2(B) C99.2(B) C100.2(B) C101.2(B) C102.2(B) C103.2(B) C104.2(B) C105.2(B) C107.2(B) C108.2(B) C115.2(B) C120.2(B) C121.2(B) C123.2(B) C124.2(B) C127.2(B) C132.2(B) C135.2(B) C137.2(B) C138.2(B) C140.2(B) C142.2(B) C143.2(B) C158.2(B) C177.2(B) C185.2(B) C186.2(B) C189.2(B) C193.2(B) C197.2(B) C198.2(B) C199.2(B) C243.2(B) C245.2(B) C255.1(A) C257.2(B) C263.2(B) C264.2(B) C270.2(B) C275.2(B) C282.2(B) C283.2(B) C316.2(B) C317.2(B) C320.2(B) C323.2(B) C324.2(B) C339.2(B) C363.2(B) C391.2(B) D1.2(B) D3.2(GND) D6.2(B) J2.2(GND1) J2.7(GND5) J2.9(GND3) J2.10(GND2) J2.12(GND4) J4.2 J4.3 J5.2 J5.3 J12.4 J12.5(S1) J12.6(S2) J13.4(GND1) J13.7(GND2) J13.10(S1) J13.11(S2) J21.6(VSS) J21.10(DETECT_TERM) J21.11(S1) J21.12(S2) J21.13(S3) J21.14(S4) J21.15(S5) LED1.2(C) Q1.2(E) Q2.2(E) Q5.2(E) R38.1(A) R39.2(B) R41.1(A) R42.1(A) R45.2(B) R48.2(B) R50.2(B) R57.2(B) R89.2(B) R96.1(A) R145.2(B) R146.2(B) R149.2(B) R183.2(B) R210.2(B) R229.2(B) U1.A1(VSS_47) U1.A2(VSS_48) U1.AA2(VSS_100) U1.AA3(VSS_99) U1.AA8(VSS_98) U1.AA13(VSS_97) U1.AA14(VSS_92) U1.AA15(VSS_91) U1.AA17(VSS_90) U1.AA18(VSS_89) U1.AA20(VSS_96) U1.AB1(VSS_95) U1.AB4(VSS_94) U1.AB6(VSS_93) U1.AB10(VSS_54) U1.AB12(VSS_27) U1.AC1(VSS_56) U1.AC3(VSS_55) U1.AC5(VSS_59) U1.AC9(VSS_65) U1.AC11(VSS_74) U1.AC23(VSS_88) U1.B20(VSS_50) U1.C3(VSS_66) U1.C13(VSS_104) U1.C20(VSS_49) U1.D9(VSS_103) U1.D13(VSS_69) U1.D19(VSS_67) U1.E4(VSS_68) U1.F4(VSS_70) U1.G3(VSS_105) U1.G4(VSS_71) U1.G12(VSS_101) U1.G13(VSS_102) U1.G16(VSS_51) U1.H3(VSS_72) U1.H10(VSS_16) U1.H11(VSS_31) U1.H12(VSS_32) U1.H13(VSS_21) U1.H14(VSS_23) U1.H15(VSS_35) U1.H20(VSS_41) U1.J2(VSS_42) U1.J10(VSS_17) U1.J11(VSS_36) U1.J12(VSS_37) U1.J15(VSS_40) U1.J20(VSS_43) U1.K1(VSS_44) U1.K3(VSS_45) U1.K5(VSS_46) U1.K10(VSS_20) U1.K11(VSS_24) U1.K12(VSS_25) U1.K15(VSS_34) U1.K16(VSS_33) U1.L3(VSS_29) U1.L4(VSS_30) U1.L11(VSS_18) U1.L12(VSS_19) U1.L15(VSS_22) U1.M6(VSS_13) U1.M8(VSS_80) U1.M11(VSS_14) U1.M12(VSS_15) U1.M15(VSS_52) U1.M20(VSS_86) U1.N2(VSS_85) U1.N3(VSS_82) U1.N5(VSS_81) U1.N15(VSS_75) U1.N16(VSS_26) U1.N17(VSS_73) U1.P1(VSS_87) U1.P5(VSS_63) U1.P16(VSS_38) U1.P19(AVSS_PLL) U1.P20(VSS_64) U1.R2(VSS_62) U1.R4(VSS_61) U1.R6(VSS_60) U1.R20(VSS_58) U1.T1(VSS_57) U1.T11(VSS_39) U1.U2(VSS_12) U1.U5(VSS_11) U1.U20(VSS_10) U1.V4(VSS_3) U1.V10(VSS_7) U1.V21(VSS_6) U1.W3(VSS_9) U1.W8(VSS_5) U1.W11(VSS_1) U1.W13(VSS_8) U1.W15(VSS_2) U1.W19(VSS_4) U1.W21(VSS_79) U1.Y1(VSS_78) U1.Y3(VSS_77) U1.Y7(VSS_28) U1.Y9(VSS_76) U1.Y18(VSS_84) U1.Y20(VSS_83) U1.Y23(VSS_53) U2.1(GND) U2.6(RFGND) U5.1(+INR) U5.4(SGND) U5.10(PGND) U5.14(+INL) U7.1(RFGND1) U7.5(GND) U10.2(GND) U12.2(GND) U19.2(NC2/VSS3) U19.13(VSS1) U19.23(NC14/VSS4) U19.25(NC16/VSS5) U19.36(VSS2) U19.48(NC29/VSS6) U22.AA4(VSS_8) U22.AA6(VSS_9) U22.K4(VSS_1) U22.M7(VSS_2) U22.P5(VSS_3) U22.R10(VSS_4) U22.U8(VSS_5) U22.Y2(VSS_6) U22.Y5(VSS_7) ; also on sheet 1 2 5 6 7 8 9 17 18 19
VDD_AUDIO: C158.1(A) C320.1(A) R66.2(B) R91.1(A) R179.2(B) U5.9(PVDD)
ADAC_VOUTL: C350.2(B) R50.1(A) ; also on sheet 9
ADAC_VOUTR: C351.1(A) R183.1(A) ; also on sheet 9
AUDIO_L: C339.1(A) R72.2(B) ; also on sheet 18
AUDIO_R: C140.1(A) R74.1(A) ; also on sheet 18
DDR_ADDR0: U1.AA12(DDR3_A9) ; also on sheet 1 2
DDR_ADDR1: U1.Y11(DDR3_A11) ; also on sheet 1 2
DDR_ADDR2: U1.W14(DDR3_A2) ; also on sheet 1 2
DDR_ADDR3: U1.AC14(DDR3_A0) ; also on sheet 1 2
DDR_ADDR4: U1.W12(DDR3_A15) ; also on sheet 1 2
DDR_ADDR5: U1.Y15(DDR3_A13) ; also on sheet 1 2
DDR_ADDR6: U1.AA10(DDR3_A6) ; also on sheet 1 2
DDR_ADDR7: U1.AB14(DDR3_A3) ; also on sheet 1 2
DDR_ADDR8: U1.AB11(DDR3_A8) ; also on sheet 1 2
DDR_ADDR9: U1.Y16(DDR3_A5) ; also on sheet 1 2
DDR_ADDR10: U1.Y8(DDR3_A10) ; also on sheet 1 2
DDR_ADDR11: U1.AB9(DDR3_A12) ; also on sheet 1 2
DDR_ADDR12: U1.Y10(DDR3_A1) ; also on sheet 1 2
DDR_ADDR13: U1.AA16(DDR3_A7) ; also on sheet 1 2
DDR_ADDR14: U1.AA11(DDR3_A14) ; also on sheet 1 2
DDR_ADDR15: U1.W10(DDR3_A4) ; also on sheet 1 2
DDR_BA0: U1.AC15(DDR3_BA0) ; also on sheet 1 2
DDR_BA1: U1.AA9(DDR3_BA1) ; also on sheet 1 2
DDR_BA2: U1.Y12(DDR3_BA2) ; also on sheet 1 2
DDR_CASN: U1.Y14(DDR3_CAS_N) ; also on sheet 1 2
DDR_CKE: R38.2(B) U1.W9(DDR3_CKE) ; also on sheet 1 2
DDR_CLK1N: R37.1(A) ; also on sheet 1 2
DDR_CLK1P: R36.1(A) ; also on sheet 1 2
DDR_CSN: U1.AC12(DDR3_CS_N_0) ; also on sheet 1 2
DDR_DM0: U1.K4(DDR3_DM0) ; also on sheet 2
DDR_DM1: U1.L5(DDR3_DM1) ; also on sheet 2
DDR_DM2: U1.AA1(DDR3_DM2) ; also on sheet 1
DDR_DM3: U1.Y2(DDR3_DM3) ; also on sheet 1
DDR_DQ0: U1.H4(DDR3_DQ0) ; also on sheet 2
DDR_DQ1: U1.N1(DDR3_DQ1) ; also on sheet 2
DDR_DQ2: U1.H1(DDR3_DQ2) ; also on sheet 2
DDR_DQ3: U1.P3(DDR3_DQ3) ; also on sheet 2
DDR_DQ4: U1.H5(DDR3_DQ4) ; also on sheet 2
DDR_DQ5: U1.R3(DDR3_DQ5) ; also on sheet 2
DDR_DQ6: U1.H2(DDR3_DQ6) ; also on sheet 2
DDR_DQ7: U1.P2(DDR3_DQ7) ; also on sheet 2
DDR_DQ8: U1.M4(DDR3_DQ8) ; also on sheet 2
DDR_DQ9: U1.K2(DDR3_DQ9) ; also on sheet 2
DDR_DQ10: U1.M5(DDR3_DQ10) ; also on sheet 2
DDR_DQ11: U1.J3(DDR3_DQ11) ; also on sheet 2
DDR_DQ12: U1.N4(DDR3_DQ12) ; also on sheet 2
DDR_DQ13: U1.J4(DDR3_DQ13) ; also on sheet 2
DDR_DQ14: U1.P4(DDR3_DQ14) ; also on sheet 2
DDR_DQ15: U1.J5(DDR3_DQ15) ; also on sheet 2
DDR_DQ16: U1.T5(DDR3_DQ16) ; also on sheet 1
DDR_DQ17: U1.AA5(DDR3_DQ17) ; also on sheet 1
DDR_DQ18: U1.T2(DDR3_DQ18) ; also on sheet 1
DDR_DQ19: U1.AB5(DDR3_DQ19) ; also on sheet 1
DDR_DQ20: U1.R5(DDR3_DQ20) ; also on sheet 1
DDR_DQ21: U1.AC6(DDR3_DQ21) ; also on sheet 1
DDR_DQ22: U1.T3(DDR3_DQ22) ; also on sheet 1
DDR_DQ23: U1.AA6(DDR3_DQ23) ; also on sheet 1
DDR_DQ24: U1.AA4(DDR3_DQ24) ; also on sheet 1
DDR_DQ25: U1.U1(DDR3_DQ25) ; also on sheet 1
DDR_DQ26: U1.AB3(DDR3_DQ26) ; also on sheet 1
DDR_DQ27: U1.U3(DDR3_DQ27) ; also on sheet 1
DDR_DQ28: U1.AC2(DDR3_DQ28) ; also on sheet 1
DDR_DQ29: U1.T4(DDR3_DQ29) ; also on sheet 1
DDR_DQ30: U1.AB2(DDR3_DQ30) ; also on sheet 1
DDR_DQ31: U1.U4(DDR3_DQ31) ; also on sheet 1
DDR_DQS0N: U1.L1(DDR3_DQS0_N) ; also on sheet 2
DDR_DQS0P: U1.L2(DDR3_DQS0_P) ; also on sheet 2
DDR_DQS1N: U1.M3(DDR3_DQS1_N) ; also on sheet 2
DDR_DQS1P: U1.M2(DDR3_DQS1_P) ; also on sheet 2
DDR_DQS2N: U1.V2(DDR3_DQS2_N) ; also on sheet 1
DDR_DQS2P: U1.V3(DDR3_DQS2_P) ; also on sheet 1
DDR_DQS3N: U1.W2(DDR3_DQS3_N) ; also on sheet 1
DDR_DQS3P: U1.W1(DDR3_DQS3_P) ; also on sheet 1
DDR_ODT: U1.AB15(DDR3_ODT_0) ; also on sheet 1 2
DDR_PLL: C11.1(A) C264.1(A) C270.1(A) LB7.1(A) U1.N8(AVDD_DDRPLL1) U1.T12(AVDD_DDRPLL2)
DDR_RASN: U1.AB16(DDR3_RAS_N) ; also on sheet 1 2
DDR_RESETN: R24.1(A) U1.AB13(DDR3_RESET_N) ; also on sheet 1 2
DDR_WEN: U1.Y13(DDR3_WE_N) ; also on sheet 1 2
IR_IN: D3.1(OUT) R140.1(A) ; also on sheet 8
LED_GREEN: R3.2(B) R22.1(A) R48.1(A) ; also on sheet 8
LED_RED: R31.1(A) R39.1(A) R60.2(B) ; also on sheet 8
MUTE_CTRL: R90.1(A) ; also on sheet 9
NF_ALE_EMMC_PWREN: U19.17(ALE) ; also on sheet 8
NF_CLE: U19.16(CLE) ; also on sheet 8
NF_CSN0_EMMC_CMD: R212.2(B) U19.9(~{CE}) U22.W5(CMD) ; also on sheet 8
NF_DQ0_EMMC_D0: R189.2(B) U19.29(I/O0) U22.H3(DAT0) ; also on sheet 8
NF_DQ1_EMMC_D1: R12.2(B) U19.30(I/O1) U22.H4(DAT1) ; also on sheet 8
NF_DQ2_EMMC_D2: R29.2(B) U19.31(I/O2) U22.H5(DAT2) ; also on sheet 8
NF_DQ3_EMMC_D3: R58.2(B) U19.32(I/O3) U22.J2(DAT3) ; also on sheet 8
NF_DQ4_EMMC_D4: R176.2(B) U19.41(I/O4) U22.J3(DAT4) ; also on sheet 8
NF_DQ5_EMMC_D5: R177.2(B) U19.42(I/O5) U22.J4(DAT5) ; also on sheet 8
NF_DQ6_EMMC_D6: R188.2(B) U19.43(I/O6) U22.J5(DAT6) ; also on sheet 8
NF_DQ7_EMMC_D7_BOOT_SEL0: R202.2(B) U19.44(I/O7) U22.J6(DAT7) ; also on sheet 8
NF_RDY0_EMMC_RST: C115.1(A) R203.2(B) U19.7(R/B~) U22.U5(RSTN) ; also on sheet 8
NF_REN_EMMC_CLK: U19.8(~{RE}) U22.W6(CLK) ; also on sheet 8
NF_WEN_EMMC_DET: U19.18(~{WE}) ; also on sheet 8
NF_WP: R89.1(A) R215.2(B) U19.19(~{WP})
RF0: C64.1(A) L1.2(B) U7.3(RF0)
RF1: C50.1(A) L7.2(B) U2.7(RF) U7.2(RF1)
RFF0: C61.1(A) J5.1 L1.1(A)
RFF1: C60.1(A) J4.1 L7.1(A)
SDIO0_CARD_DETECT: J21.9(SWITCH_TERM) R155.2(B) ; also on sheet 8
SDIO0_CCLK_OUT: J21.5(CLK) ; also on sheet 8
SDIO0_CCMD: J21.3(CMD) R153.2(B) ; also on sheet 8
SDIO0_CDATA0: J21.7(DAT0) R152.2(B) ; also on sheet 8
SDIO0_CDATA1: J21.8(DAT1) R151.2(B) ; also on sheet 8
SDIO0_CDATA2: J21.1(DATA2) R156.2(B) ; also on sheet 8
SDIO0_CDATA3: J21.2(CD/DAT3) R154.2(B) ; also on sheet 8
SDIO0_PWREN: R76.1(A) R149.1(A) ; also on sheet 8
SDIO_3318: R151.1(A) R152.1(A) R153.1(A) R154.1(A) R156.1(A) ; also on sheet 8
USB0_DM: C95.1(A) D6.1(A) J12.2 ; also on sheet 9
USB0_DP: C92.1(A) D1.1(A) J12.3 ; also on sheet 9
USB1_DM: J2.4(D-) U2.4(DM) U7.7(DM) ; also on sheet 9
USB1_DP: J2.3(D+) U2.2(DP) U7.6(DP) ; also on sheet 9
USB3_DM: J13.2(D-) ; also on sheet 8
USB3_DP: J13.3(D+) ; also on sheet 8
USB3_RXN: J13.5(RX-) ; also on sheet 8
USB3_RXP: J13.6(RX+) ; also on sheet 8
USB3_TXN: C77.2(B) ; also on sheet 8
USB3_TXP: C81.2(B) ; also on sheet 8
N01881: R49.2(B) R57.1(A) R91.2(B)
N01893: C54.1(A) R20.1(A) R72.1(A) R145.1(A) U5.12(OUTL)
N01945: C32.2(B) U5.8(CP)
N01953: C32.1(A) U5.7(CN)
N01961: C33.2(B) U5.6(PVSS)
N01965: C363.1(A) R66.1(A) R90.2(B) R229.1(A) U5.5(EN)
N01987: C55.2(B) R19.2(B) R74.2(B) R146.1(A) U5.3(OUTR)
N02013: C317.1(A) R19.1(A) R27.1(A) R193.2(B)
N02033: C55.1(A) R27.2(B) U5.2(-INR)
N02043: C351.2(B) R193.1(A)
N02063: C54.2(B) R28.1(A) U5.13(-INL)
N02073: C316.1(A) R20.2(B) R28.2(B) R194.1(A)
N02085: C350.1(A) R194.2(B)
N02089: R49.1(A) U5.11(UVP)
N02814: C73.2(B) Q15.1(G) R77.2(B) R267.1(A)
N02844: Q5.3(C) R267.2(B)
N02848: Q5.1(B) R76.2(B)
N02874: C47.1(A) C177.1(A) D3.3(VCC) R178.1(A)
N02960: Q1.1(B) R22.2(B)
N02964: Q2.1(B) R31.2(B)
N02968: LED1.3(A2) Q1.3(C) R2.2(B)
N02980: LED1.1(A1) Q2.3(C) R34.2(B)
N03644: R42.2(B) U12.4(ILIM)
N03926: R11.1(A) U12.3(EN)
N03950: R41.2(B) U10.4(ILIM)
N03956: R15.1(A) U10.3(EN)
N03990: C29.1(A) C52.1(A) J12.1 LB2.1 U10.5(OUT)
N04006: C38.1(A) C75.1(A) J13.1(VBUS) LB3.1 U12.5(OUT)
N05486: R68.1(A) U19.39(NC24)
N12433: C255.2(B) U1.T19(DVDD11_LDO_DECAP)
N13716: R37.2(B) U1.AB7(DDR3_CLK1_N)
N13720: R36.2(B) U1.AA7(DDR3_CLK1_P)
N466746: R45.1(A) U1.W16(DDR3_ZQ)
N3765204: C123.1(A) C124.1(A) U22.K2(VDDI)
N16822958: C77.1(A) J13.8(TX-)
N16822960: C81.1(A) J13.9(TX+)
N16883367: R80.2(B) U19.38(NC23/VDDQ2)

Not connected (* = marked no-connect by the designer): J2 1(NC1)* 6(NC2)* 8(RF0)* 11(RF1)*; U1 AB8(DDR3_CLK0_N)* AC8(DDR3_CLK0_P)*; U2 3(VDD+)*; U7 4(XI)* 9(SUSPEND)* 10(WO_WLAN)*; U19 3(NC3)* 4(NC4)* 5(NC5)* 6(NC6)* 10(NC7)* 11(NC8)* 14(NC9)* 15(NC10)* 20(NC11)* 21(NC12)* 22(NC13)* 26(NC17) 27(NC18) 28(NC19) 33(NC20) 35(NC22)* 40(NC25) 45(NC26) 46(NC27) 47(NC28); U22 A4(NC_1)* A6(NC_2)* A9(NC_3)* A11(NC_4)* AA1(NC_122)* AA2(NC_123)* AA7(NC_124)* AA8(NC_125)* AA9(NC_126)* AA10(NC_127)* AA11(NC_128)* AA12(NC_129)* AA13(NC_130)* AA14(NC_131)* AE1(NC_132)* AE14(NC_133)* AG2(NC_134)* AG13(NC_135)* AH4(NC_136)* AH6(NC_137)* AH9(NC_138)* AH11(NC_95)* B2(NC_5)* B13(NC_6)* D1(NC_7)* D14(NC_8)* H1(NC_9)* H2(NC_10)* H6(NC_11)* H7(NC_12)* H8(NC_13)* H9(NC_14)* H10(NC_15)* H11(NC_16)* H12(NC_17)* H13(NC_18)* H14(NC_19)* J1(NC_20)* J7(NC_21)* J8(NC_22)* J9(NC_23)* J10(NC_24)* J11(NC_25)* J12(NC_26)* J13(NC_27)* J14(NC_28)* K1(NC_29)* K3(NC_30)* K5(NC_31)* K7(NC_32)* K8(NC_33)* K9(NC_34)* K10(NC_35)* K11(NC_36)* K12(NC_37)* K13(NC_38)* K14(NC_39)* L1(NC_40)* L2(NC_41)* L3(NC_42)* L4(A1)* L12(NC_43)* L13(NC_44)* L14(NC_45)* M1(NC_46)* M2(NC_47)* M3(NC_48)* M5(NC_49)* M8(NC_50)* M9(NC_51)* M10(NC_52)* M12(NC_53)* M13(NC_54)* M14(NC_55)* N1(NC_56)* N2(NC_57)* N3(NC_58)* N10(NC_59)* N12(NC_60)* N13(NC_61)* N14(NC_62)* P1(NC_63)* P2(NC_64)* P3(NC_65)* P10(NC_66)* P12(NC_67)* P13(NC_68)* P14(NC_69)* R1(NC_70)* R2(NC_71)* R3(NC_72)* R5(NC_73)* R12(NC_74)* R13(NC_75)* R14(NC_76)* T1(NC_77)* T2(NC_78)* T3(NC_79)* T5(NC_80)* T12(NC_81)* T13(NC_82)* T14(NC_83)* U1(NC_84)* U2(NC_85)* U3(NC_86)* U6(NC_87)* U7(NC_88)* U10(NC_89)* U12(NC_90)* U13(NC_91)* U14(NC_92)* V1(NC_93)* V2(NC_94)* V3(NC_96)* V12(NC_97)* V13(NC_98)* V14(NC_99)* W1(NC_100)* W2(NC_101)* W3(NC_102)* W7(NC_103)* W8(NC_104)* W9(NC_105)* W10(NC_106)* W11(NC_107)* W12(NC_108)* W13(NC_109)* W14(NC_110)* Y1(NC_111)* Y3(NC_112)* Y6(NC_113)* Y7(NC_114)* Y8(NC_115)* Y9(NC_116)* Y10(NC_117)* Y11(NC_118)* Y12(NC_119)* Y13(NC_120)* Y14(NC_121)*

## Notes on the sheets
sheet 10
- Unit 3 of Hi3798MV100(DDR)
- 1%
- Close to Hi3798M
- ** DDR Design guideline **
- A.general suggestion
- 1.Hi3798MV100 supports up to 2GB DDR3.
- 2.DDR chip and DDR controller both need at least one 10uF decoupling ceramic capacitor.
- 3.The ciruit of DDR_VREF_CA and DDR_VREF_DQ must be independent
- 4. 3V3 DDRPLL is needed.
- B.Layout suggestion
- 1. Please copy hisilicon demo board completely
sheet 11
- Unit 4 of Hi3798MV100(POWER)
sheet 12
- Unit 5 of Hi3798MV100(VSS)
sheet 13
- NAND FLASH/EMMC
- NAND FLASH
- eMMC/fSD
- fSD  10K
- 4GB
- fSD
- H6 eMMC5.0
- NFWP
- 0:Protect
- 1:NOT Protect
- 4GB
- NAND FLASH
- C142=C143=100NF,C36=1UF,R215=4.7K,R68=0,C88=100UF,D2=DIODE,U19=NAND
- others=NC,If use MICRON NAND FLASH,R68=NC
- T5 eMMC5.0
- eMMC
- Pay attention to pin38&pin39,these pins are NC for the MLC NAND of some
- C63=C123=C124=C93=C105=C323=C324=100NF,C275=2.2UF
- brands(such as Micron),but it should be connected to the VCC of
- R203=R189=R12=R29=R58=R176=R177=R188=R202=47K,R212=10K,R94=0,U22=eMMC,others=NC
- others(such as Toshiba and Hynix).
- Pls refer to the corresponding datasheet for detail.
- fSD
- C63=C123=C124=C93=C105=C323=C324=100NF,C275=2.2UF
- R5 eMMC5.0
- R203=R189=R12=R29=R58=R212=10K,R94=0,U22=fSD,others=NC
sheet 14
- USB2.0/USB3.0/WIFI
- ETA6010:Current=1.3A
- USB0:usb_boot/adb
- For Board Antenna
- ANTF:50ohm Resistance
- ETA6010:Current=1.3A
- For Board Antenna
- ANTF:50ohm Resistance
sheet 15
- SD CARD/IR
- LED
- IR
- R ON+G OFF->STBY
- GREEN
- R OFF+G ON->WORK
- R OFF+G OFF->NO POWER
- RED
sheet 16
- Audio Output
- 1%
- 1%
- 1%
- 1%
- 1%
- MUTE_CTL
- 0
- Mute
- 1
- Work
